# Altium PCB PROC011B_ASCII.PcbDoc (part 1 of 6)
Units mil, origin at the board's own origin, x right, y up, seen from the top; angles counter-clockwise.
Board outline 3304 x 2569 mil, 6 copper layers (TOP, L2-GND1, L3-GND/SIG, L4-GND/SIG, L5-GND2, BOTTOM), stack 55.77 mil thick; 376 components, 289 nets, 1284 pads, 1755 vias.
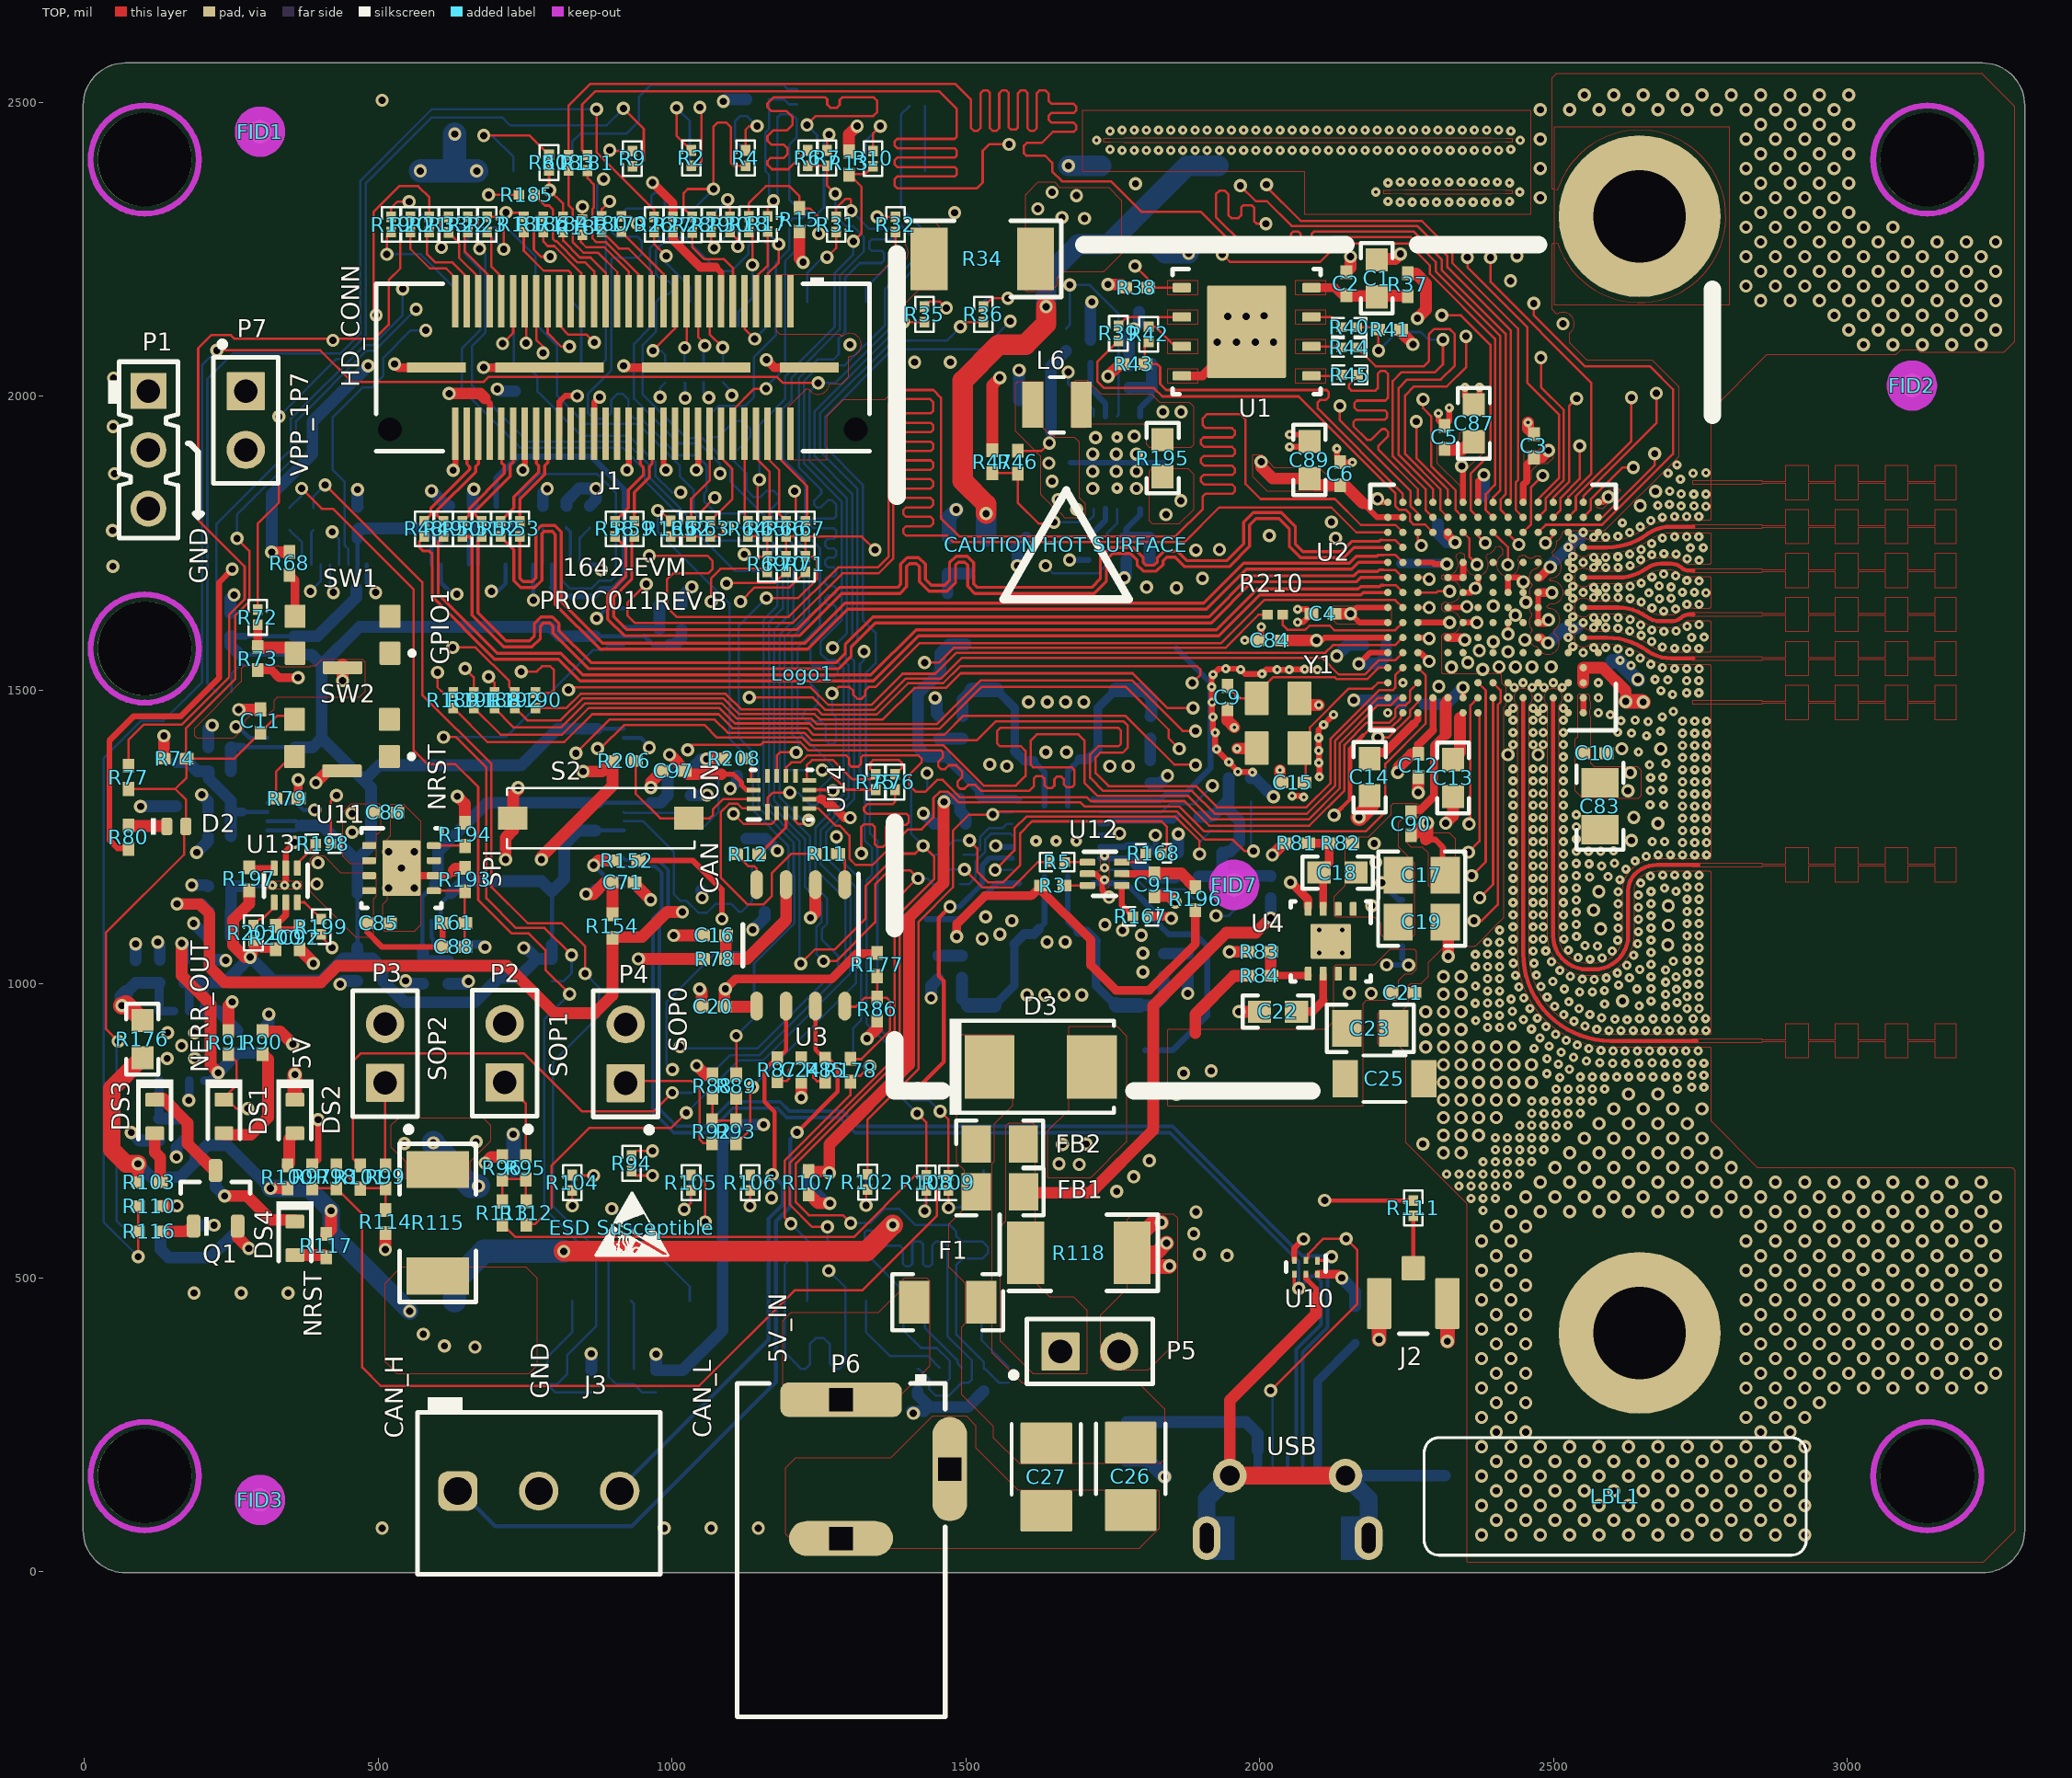
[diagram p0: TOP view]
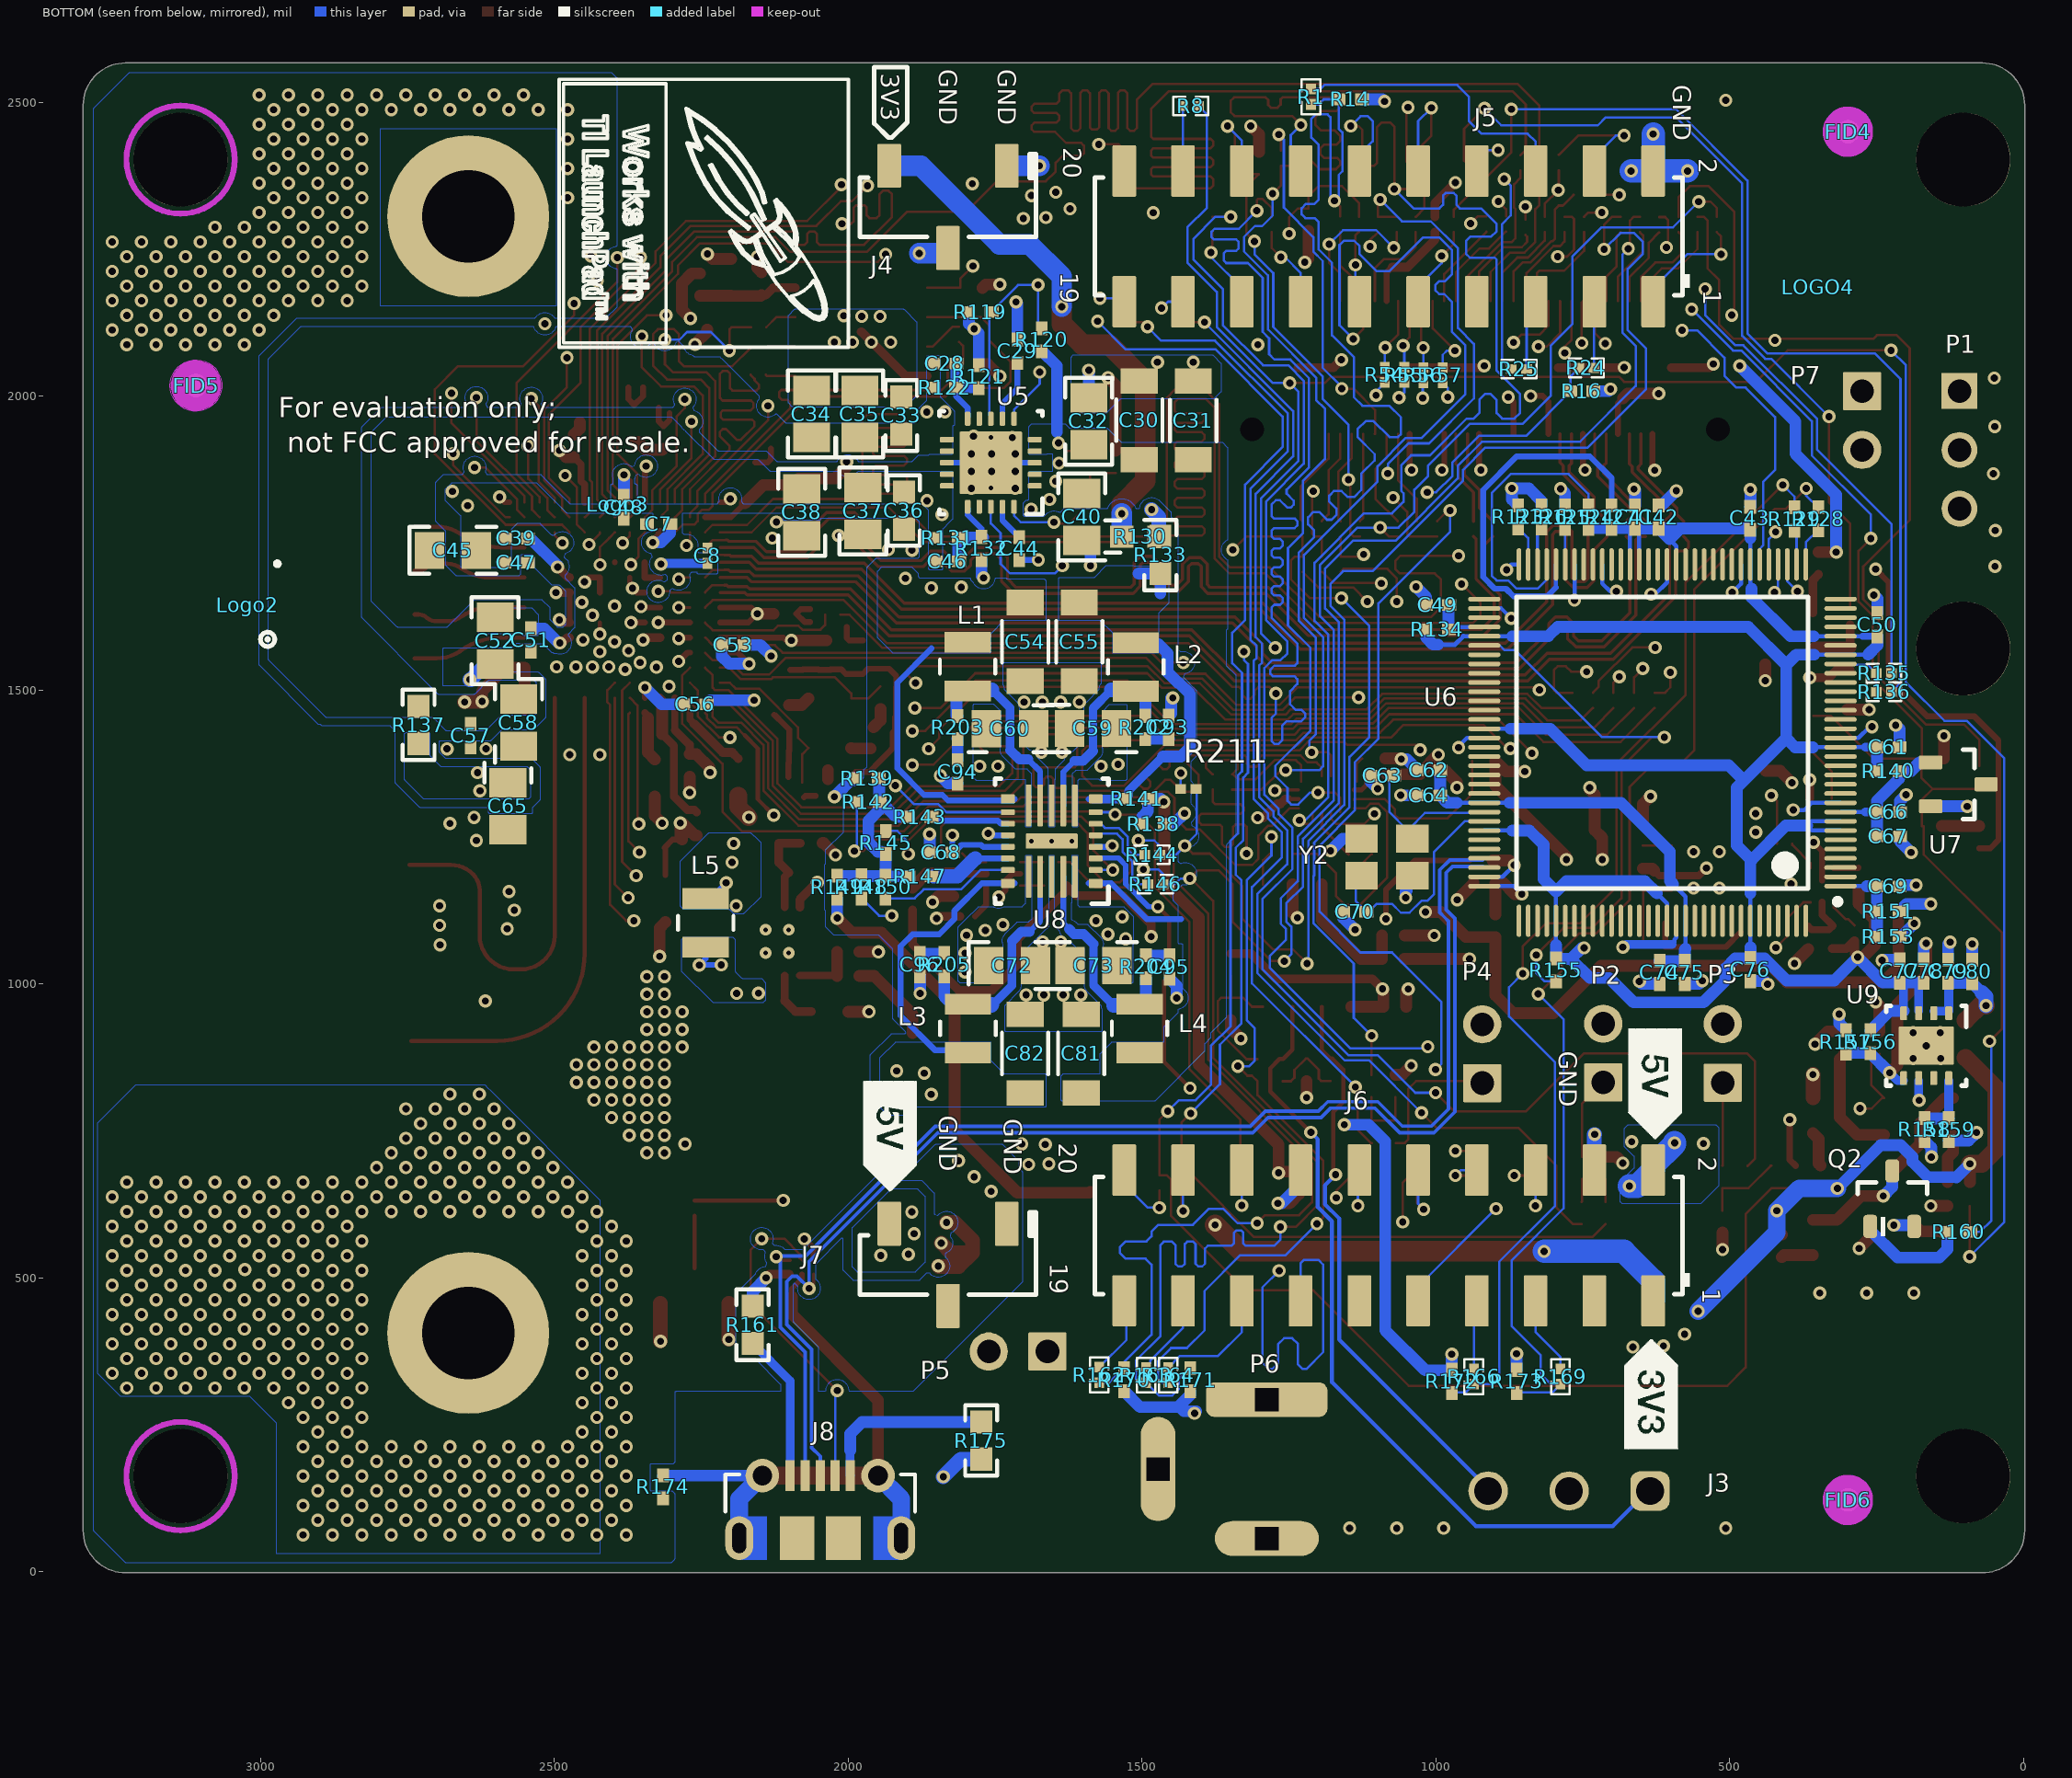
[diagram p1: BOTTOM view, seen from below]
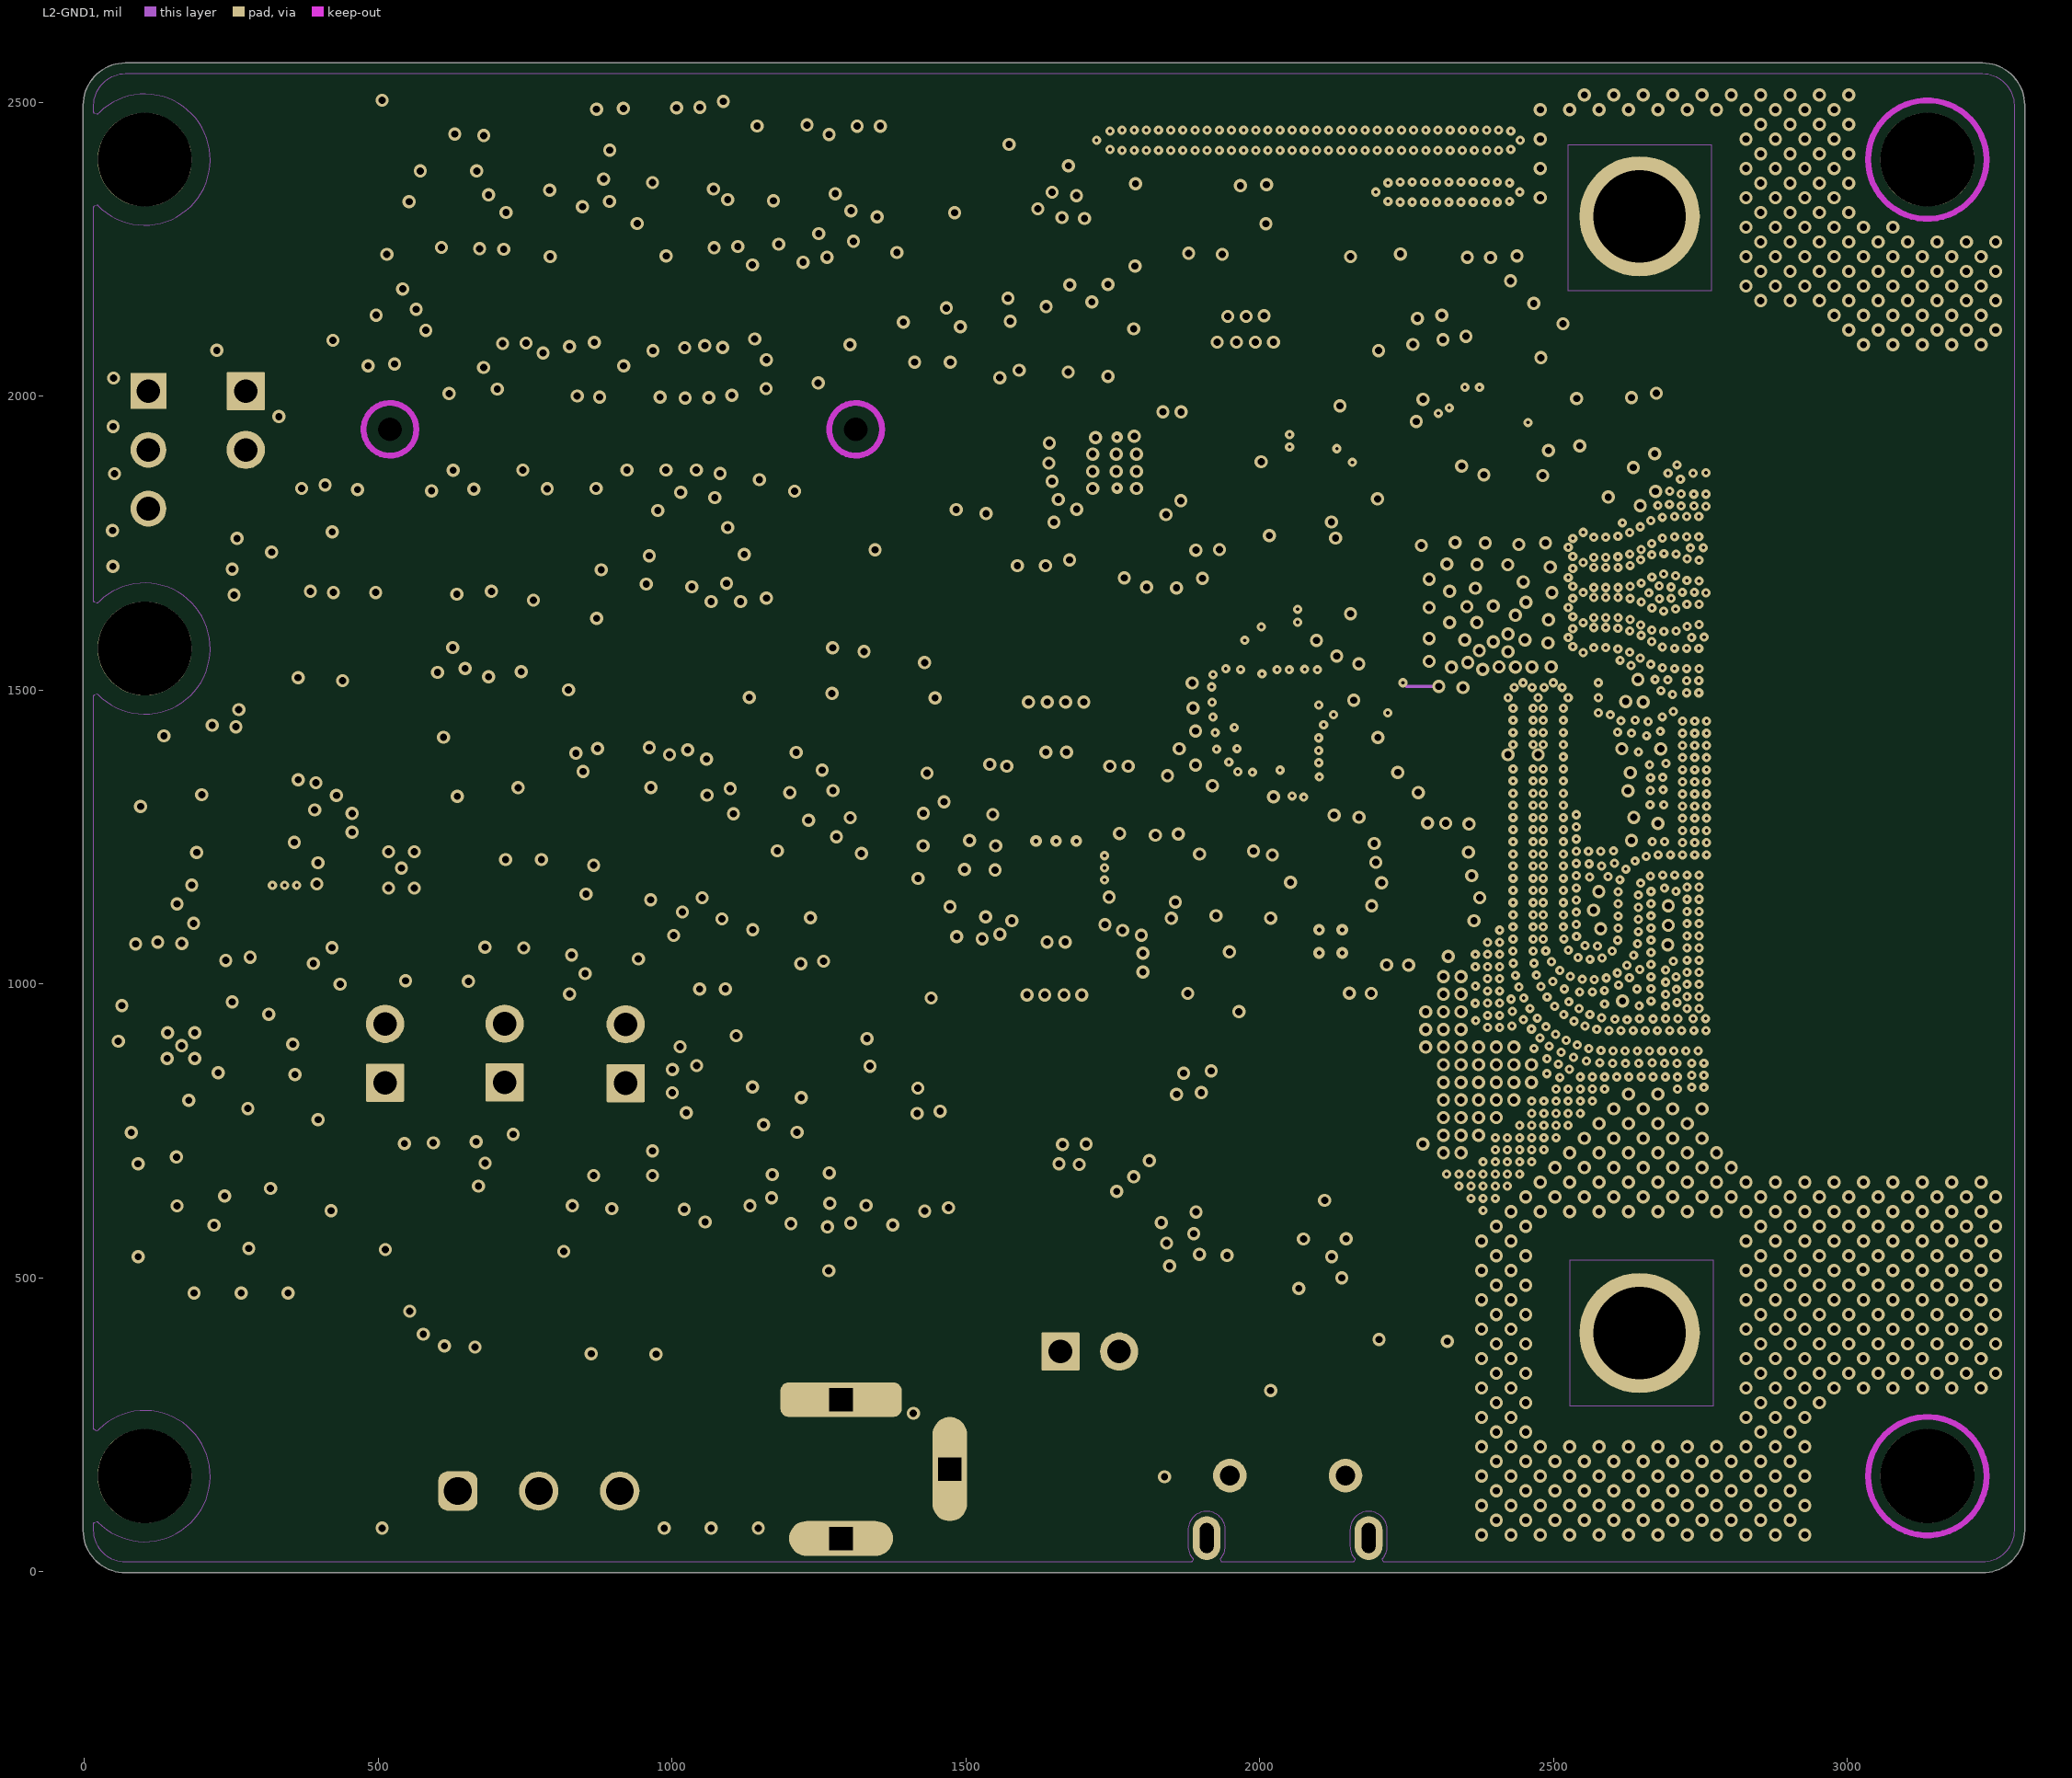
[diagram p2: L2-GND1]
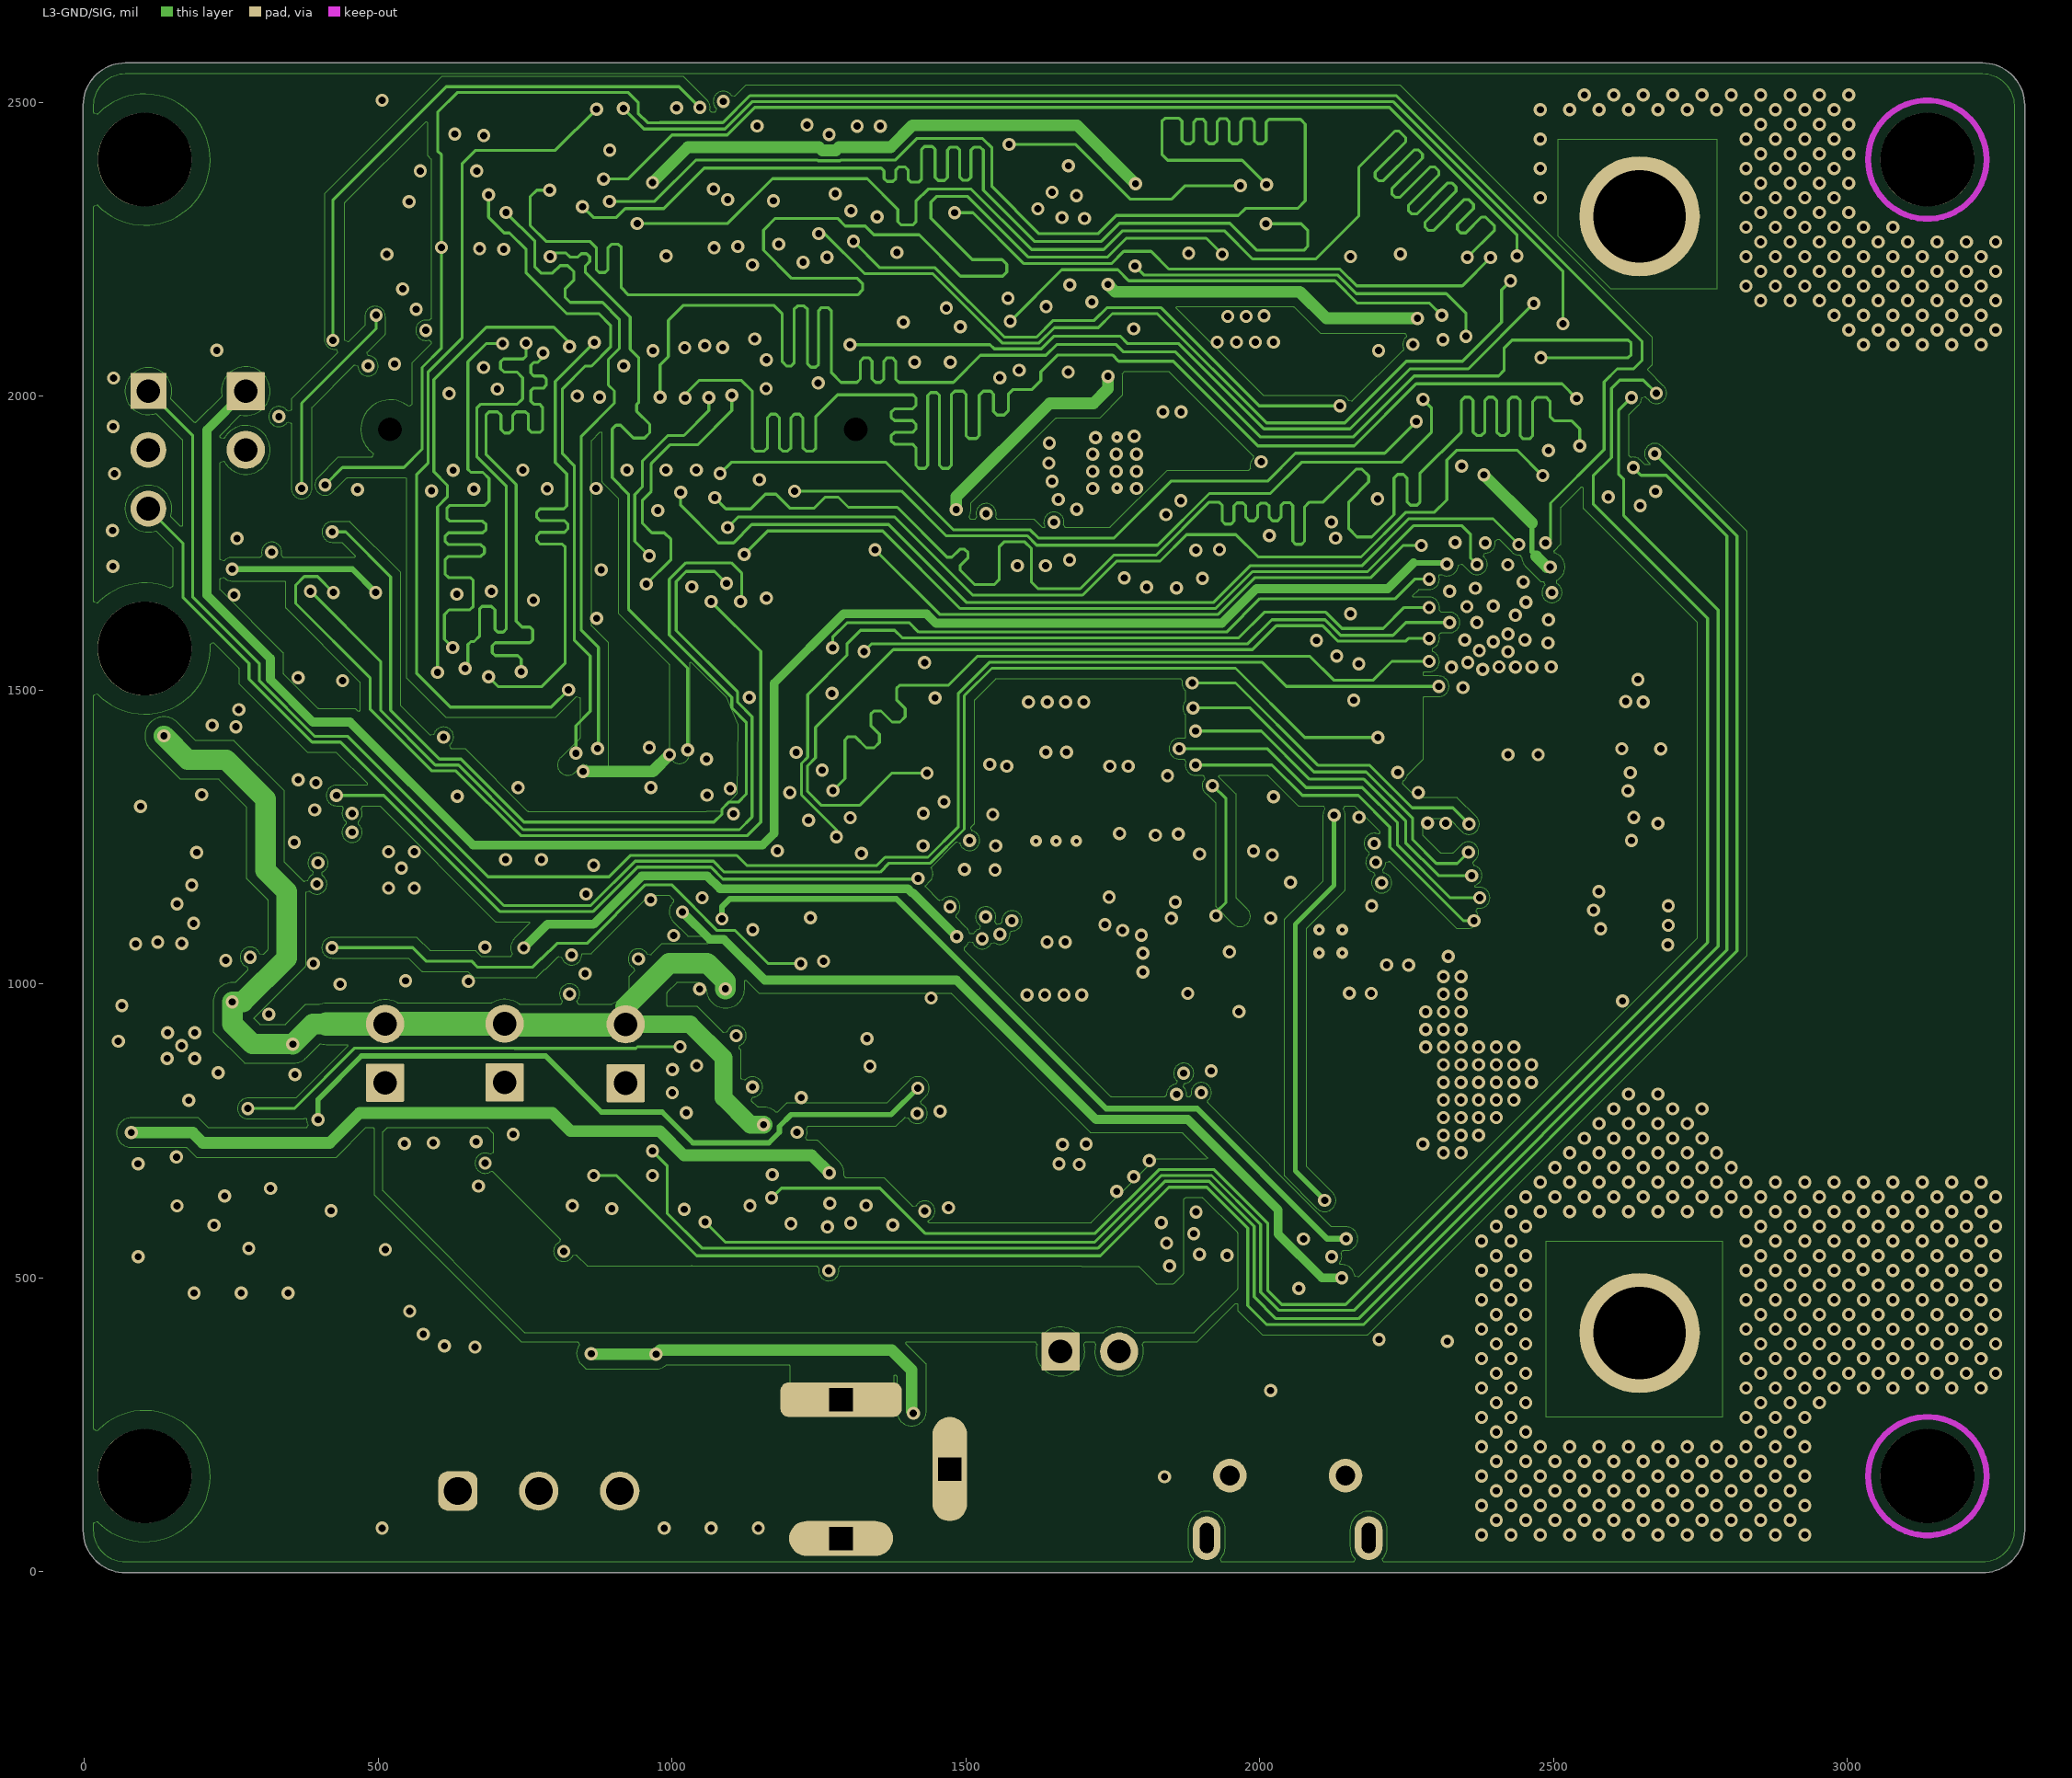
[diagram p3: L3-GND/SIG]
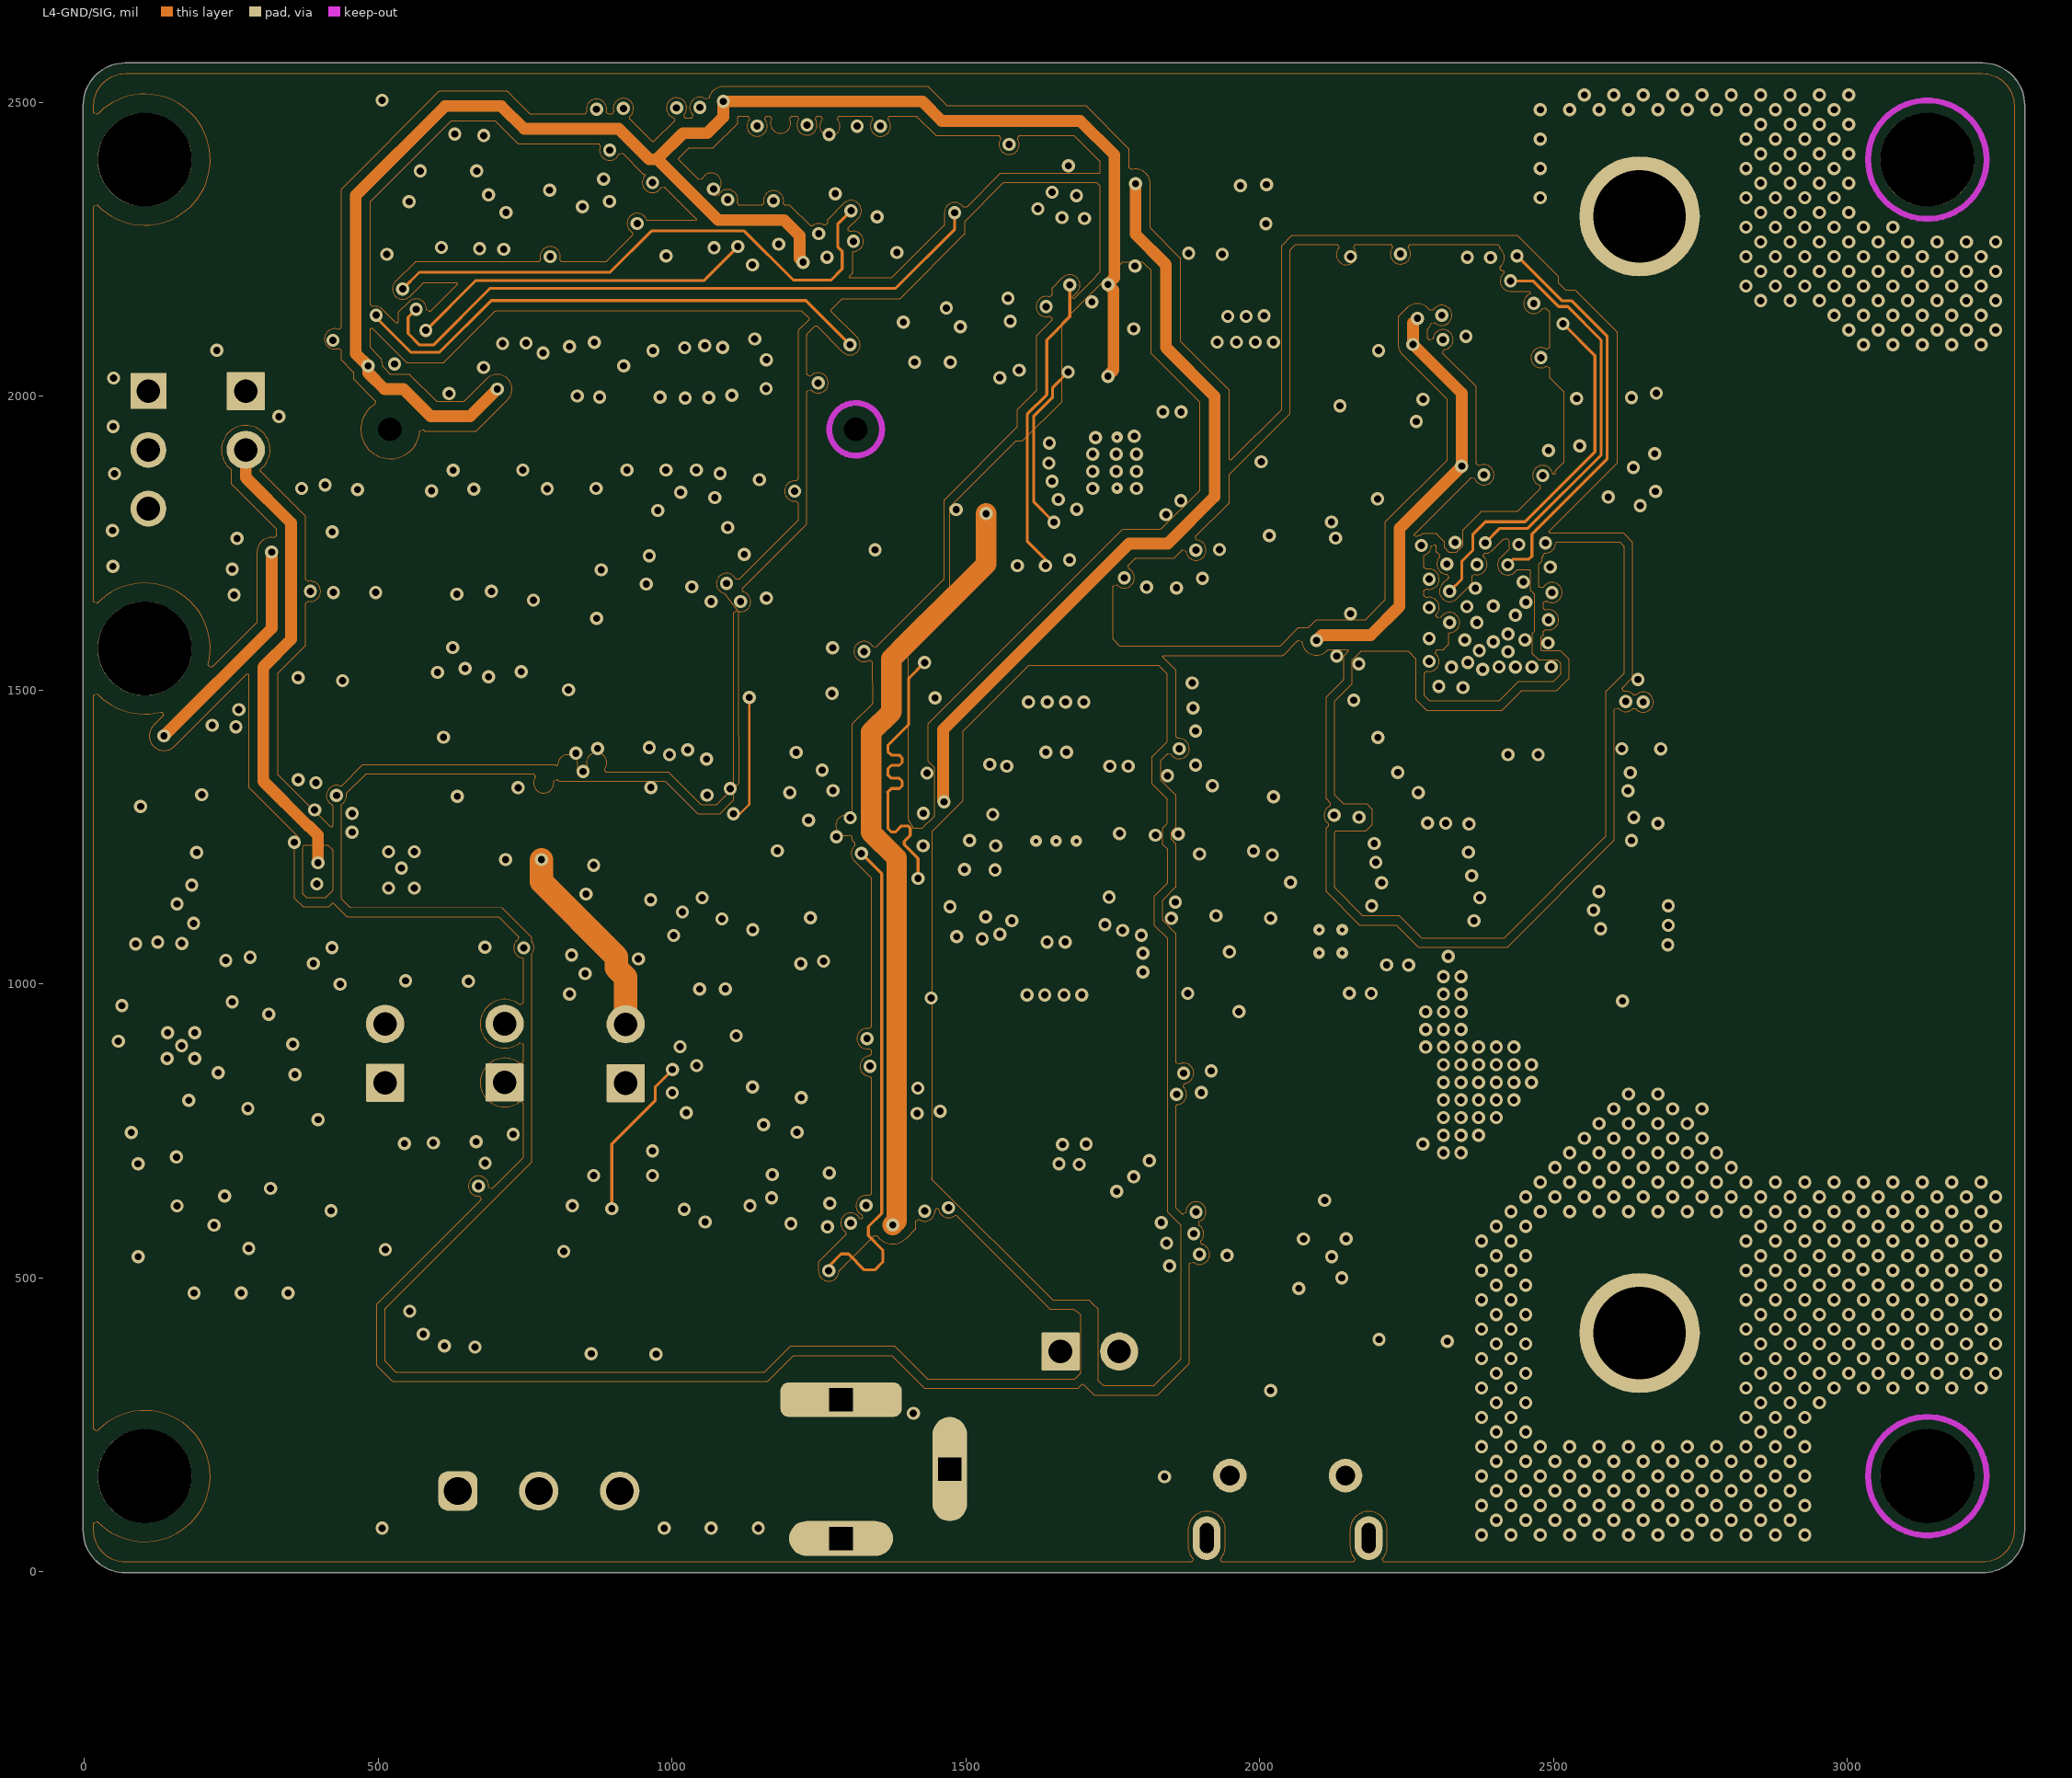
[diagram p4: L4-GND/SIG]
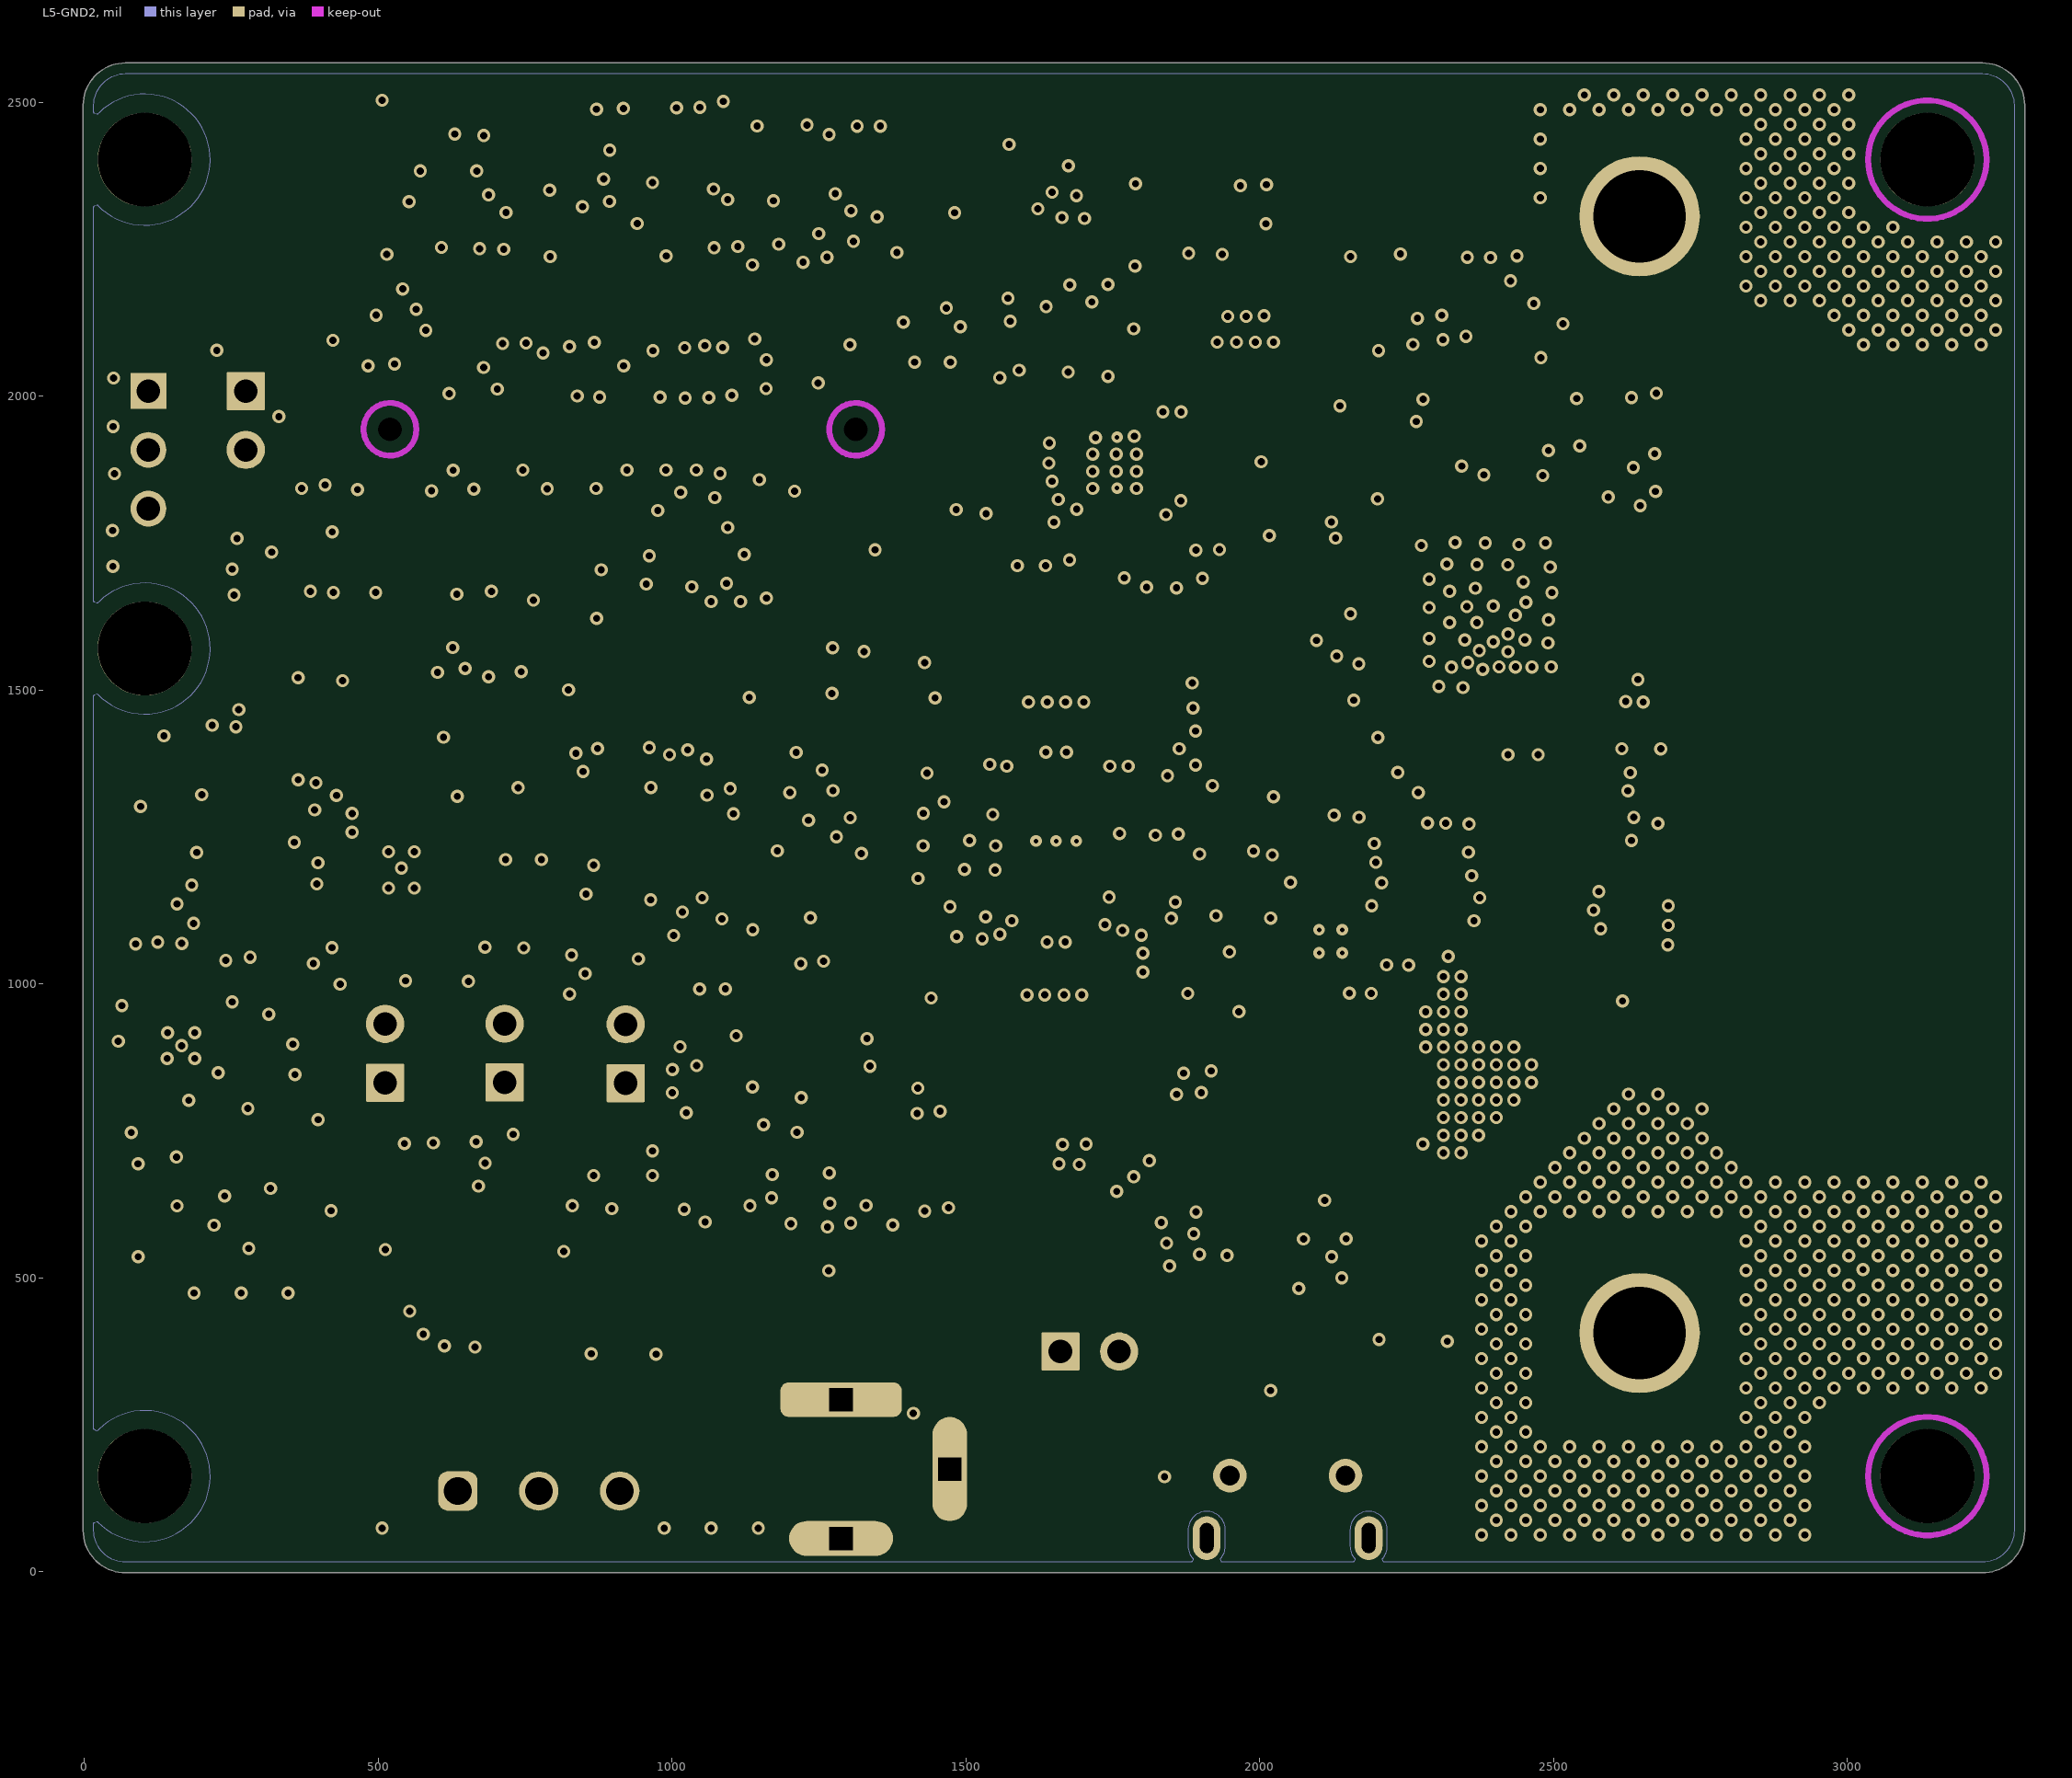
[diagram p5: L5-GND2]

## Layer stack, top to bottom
Top Solder: solder mask 0.8, Solder Resist, Dk 0
TOP: signal copper 1.6
Dielectric1: core 4, RO4835 LOPRO, Dk 3.66
L2-GND1: signal copper 1.4
Dielectric2: prepreg 5.67, 370HR, Dk 3.9
L3-GND/SIG: signal copper 1.2
Dielectric3: core 28, 370HR, Dk 4.36
L4-GND/SIG: signal copper 1.2
Dielectric4: prepreg 5.9, 370HR, Dk 3.9
L5-GND2: signal copper 1.2
Dielectric5: core 4, 370HR, Dk 4.26
BOTTOM: signal copper 1.6
Bottom Solder: solder mask 0.8, Solder Resist, Dk 0

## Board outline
-2,70 ccw(c70,70) 70,-2 3230,-2 ccw(c3230,70) 3302,70 3302,2495 ccw(c3230,2495) 3230,2567 70,2567 ccw(c70,2495) -2,2495

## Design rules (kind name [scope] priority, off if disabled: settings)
AcuteAngle [All] p0: scope1count=1 scope1_0_kind=Board scope1_0_value=Board scope2count=1 scope2_0_kind=Board scope2_0_value=Board commentlength=0 minimum=4.50000000000000E+0001
AcuteAngle [All] p1: minimum=4.50000000000000E+0001 checktracksonly=FALSE
AssemblyTestPointUsage [All] p0: scope1count=1 scope1_0_kind=Board scope1_0_value=Board scope2count=1 scope2_0_kind=Board scope2_0_value=Board commentlength=0
AssemblyTestpoint [All] p0: scope1count=1 scope1_0_kind=Board scope1_0_value=Board scope2count=1 scope2_0_kind=Board scope2_0_value=Board commentlength=0
Clearance COPLANNER [All] p0 off: scope1count=1 scope1_0_kind=Board scope1_0_value=Board scope2count=1 scope2_0_kind=Board scope2_0_value=Board commentlength=59 gap=3 // Protel DXP Scope 1 Expression Was: WithinRoom('COUPLE')
Clearance Clearance_PMIC [All] p0 off: scope1count=1 scope1_0_kind=Board scope1_0_value=Board scope2count=1 scope2_0_kind=Board scope2_0_value=Board commentlength=70 gap=5 // Protel DXP Scope 1 Expression Was: WithinRoom('Copper to PMIC IC')
Clearance same_net_cl_inner [All] p0 off: scope1count=1 scope1_0_kind=Board scope1_0_value=Board scope2count=1 scope2_0_kind=Board scope2_0_value=Board commentlength=61 gap=10 // Protel DXP Scope 1 Expression Was: InLayerClass('layers')
Clearance Clearance_TOP [All] p0: scope1count=1 scope1_0_kind=Layer scope1_0_value=TOP scope2count=1 scope2_0_kind=Board scope2_0_value=Board commentlength=0 gap=10
Clearance Clearance_1 [All] p0 off: scope1count=1 scope1_0_kind=Board scope1_0_value=Board scope2count=1 scope2_0_kind=Board scope2_0_value=Board commentlength=69 gap=6.71 // Protel DXP Scope 1 Expression Was: WithinRoom('DUT') OR InPolygon
Clearance RX_TX_TOP [All] p0: scope1count=1 scope1_0_kind=Layer scope1_0_value=TOP scope2count=1 scope2_0_kind=NetClass scope2_0_value=RX_TX commentlength=0 gap=10
Clearance RX_TX_L25 [All] p0 off: scope1count=1 scope1_0_kind=Board scope1_0_value=Board scope2count=1 scope2_0_kind=NetClass scope2_0_value=RX_TX commentlength=60 gap=10 // Protel DXP Scope 1 Expression Was: InLayerClass('L2_L5')
Clearance RX_TX_L34 [All] p0 off: scope1count=1 scope1_0_kind=Board scope1_0_value=Board scope2count=1 scope2_0_kind=NetClass scope2_0_value=RX_TX commentlength=60 gap=10 // Protel DXP Scope 1 Expression Was: InLayerClass('L3_L4')
Clearance Clearance_L25 [All] p0 off: scope1count=1 scope1_0_kind=Board scope1_0_value=Board scope2count=1 scope2_0_kind=Board scope2_0_value=Board commentlength=60 gap=15 // Protel DXP Scope 1 Expression Was: InLayerClass('L2_L5')
Clearance Clearance_L34 [All] p0 off: scope1count=1 scope1_0_kind=Board scope1_0_value=Board scope2count=1 scope2_0_kind=Board scope2_0_value=Board commentlength=60 gap=15 // Protel DXP Scope 1 Expression Was: InLayerClass('L3_L4')
Clearance Clearance_BTM [All] p0: scope1count=1 scope1_0_kind=Layer scope1_0_value=BOTTOM scope2count=1 scope2_0_kind=Board scope2_0_value=Board commentlength=0 gap=15
Clearance Clearance_L34 [InLayerClass('L3_L4')] p1: gap=15 ignorepadtopadclearanceinfootprint=FALSE except(0: Arc-Hole Track-Hole SMDPad-Hole THPad-Hole Via-Hole Fill-Hole Poly-Hole Region-Hole Text-Hole; 5: Arc-Track Arc-SMDPad Track-Track Track-SMDPad; 5.9: Via-Via; 6: Arc-Arc Arc-THPad Arc-Via Track-THPad Track-Via SMDPad-SMDPad SMDPad-THPad SMDPad-Via SMDPad-Fill SMDPad-Poly THPad-THPad THPad-Via Via-Fill Via-Poly; 10: THPad-Fill THPad-Poly)
Clearance Clearance_PMIC [WithinRoom('Copper to PMIC IC')] p2: gap=5 ignorepadtopadclearanceinfootprint=FALSE except(0: Arc-Hole Track-Hole SMDPad-Hole THPad-Hole Via-Hole Fill-Hole Poly-Hole Region-Hole Text-Hole; 4: Arc-Track Track-Track; 4.5: Track-Via SMDPad-SMDPad)
Clearance Clearance_BTM [OnLayer('BOTTOM')] p3: gap=15 ignorepadtopadclearanceinfootprint=FALSE except(0: Arc-SMDPad Arc-Hole Track-Hole SMDPad-Hole THPad-Hole Via-Hole Fill-Hole Poly-Hole Region-Hole Text-Hole; 4: Track-SMDPad; 4.5: Arc-Via Track-Via; 5: Arc-Arc Arc-Track Track-Track SMDPad-Via; 6: Arc-THPad Track-THPad SMDPad-SMDPad SMDPad-THPad THPad-THPad THPad-Via; 8: Arc-Fill Arc-Poly Track-Fill Track-Poly Via-Fill Via-Poly; 9: SMDPad-Fill SMDPad-Poly THPad-Fill THPad-Poly; 16.6: Via-Via)
Clearance Clearance_L25 [InLayerClass('L2_L5')] p4: gap=15 ignorepadtopadclearanceinfootprint=FALSE except(0: Arc-Hole Track-Hole SMDPad-Hole THPad-Hole Via-Hole Fill-Hole Poly-Hole Region-Hole Text-Hole; 5: Arc-Track Arc-SMDPad Track-Track Track-SMDPad; 6: Arc-Arc Arc-THPad Arc-Via Track-THPad Track-Via SMDPad-SMDPad SMDPad-THPad SMDPad-Via SMDPad-Fill SMDPad-Poly THPad-THPad THPad-Via Via-Via Via-Fill Via-Poly; 10: THPad-Fill THPad-Poly)
Clearance RX_TX_L34 [InLayerClass('L3_L4') vs InNetClass('RX_TX')] p5: gap=10 ignorepadtopadclearanceinfootprint=FALSE except(0: Arc-Hole Track-Hole SMDPad-Hole THPad-Hole Via-Hole Fill-Hole Poly-Hole Region-Hole Text-Hole; 4.86: Via-Via; 5: Arc-SMDPad Track-SMDPad; 6: Arc-Arc Arc-Track Arc-THPad Arc-Via Track-Track Track-THPad Track-Via SMDPad-SMDPad SMDPad-THPad SMDPad-Via SMDPad-Fill SMDPad-Poly THPad-THPad THPad-Via Via-Fill Via-Poly; 15: Arc-Fill Arc-Poly Track-Poly Fill-Fill Fill-Poly Poly-Poly; 16: Track-Fill)
Clearance COPLANNER [WithinRoom('COUPLE')] p6: gap=3 ignorepadtopadclearanceinfootprint=FALSE except(0: Arc-Hole Track-Hole SMDPad-Hole THPad-Hole Via-Hole Fill-Hole Poly-Hole Region-Hole Text-Hole)
Clearance Clearance_1 [WithinRoom('DUT') OR InPolygon] p7: gap=6.71 ignorepadtopadclearanceinfootprint=FALSE except(0: Arc-Hole Track-Hole SMDPad-Hole THPad-Hole Via-Hole Fill-Hole Poly-Hole Region-Hole Text-Hole; 4: Track-Track Track-SMDPad Track-Via SMDPad-Via; 6.6: Via-Region; 6.72: Arc-Region Arc-Text Track-Region Track-Text SMDPad-Region SMDPad-Text THPad-Region THPad-Text Via-Text Fill-Region Fill-Text Poly-Region Poly-Text Region-Region Region-Text Text-Text; 9: SMDPad-Poly; 10: THPad-Poly)
Clearance Clearance_TOP [OnLayer('TOP')] p8: gap=10 ignorepadtopadclearanceinfootprint=FALSE except(0: Arc-SMDPad Arc-Hole Track-Hole SMDPad-Hole THPad-Hole Via-Hole Fill-Hole Poly-Hole Region-Hole Text-Hole; 4: Arc-Arc Arc-Track Arc-Via Track-Track Track-Via; 5: Track-SMDPad SMDPad-Via; 6: Arc-THPad Track-THPad SMDPad-SMDPad SMDPad-THPad THPad-THPad THPad-Via Via-Fill Via-Poly; 8: Arc-Fill Arc-Poly Track-Fill Track-Poly; 9: SMDPad-Fill SMDPad-Poly THPad-Fill THPad-Poly; 15: Fill-Fill Fill-Poly Poly-Poly; 15.4: Via-Via)
Clearance RX_TX_L25 [InLayerClass('L2_L5') vs InNetClass('RX_TX')] p9: gap=10 ignorepadtopadclearanceinfootprint=FALSE except(0: Arc-Hole Track-Hole SMDPad-Hole THPad-Hole Via-Hole Fill-Hole Poly-Hole Region-Hole Text-Hole; 5: Arc-SMDPad Track-SMDPad; 6: Arc-Arc Arc-Track Arc-THPad Arc-Via Track-Track Track-THPad Track-Via SMDPad-SMDPad SMDPad-THPad SMDPad-Via SMDPad-Fill SMDPad-Poly THPad-THPad THPad-Via Via-Fill Via-Poly; 9.1: Via-Via; 15: Arc-Fill Arc-Poly Track-Fill Track-Poly Fill-Fill Fill-Poly Poly-Poly)
Clearance RX_TX_TOP [OnLayer('TOP') vs InNetClass('RX_TX')] p10: gap=10 ignorepadtopadclearanceinfootprint=FALSE except(0: Arc-Hole Track-Hole SMDPad-Hole THPad-Hole Via-Hole Fill-Hole Poly-Hole Region-Hole Text-Hole; 4: Arc-Track Arc-SMDPad Track-Track Track-SMDPad SMDPad-Via; 6: Arc-THPad Track-THPad SMDPad-SMDPad SMDPad-THPad THPad-THPad THPad-Via THPad-Fill THPad-Poly; 6.7: Arc-Fill Arc-Poly Track-Fill Track-Poly; 6.72: Arc-Via Track-Via Via-Fill Via-Poly; 9: SMDPad-Fill SMDPad-Poly; 15.4: Via-Via)
Clearance same_net_cl_inner [InLayerClass('layers')] p11: gap=10 ignorepadtopadclearanceinfootprint=FALSE except(0: Arc-Hole Track-Hole SMDPad-Hole THPad-Hole Via-Hole Fill-Hole Poly-Hole Region-Hole Text-Hole; 5: Arc-THPad Track-Track Track-SMDPad Track-THPad SMDPad-SMDPad SMDPad-THPad THPad-THPad; 6: Track-Via SMDPad-Via THPad-Via Via-Via Via-Fill Via-Poly; 15: Arc-Fill Arc-Poly Fill-Fill Fill-Poly Poly-Poly)
ComponentClearance ComponentClearance_1 [All] p0: scope1count=1 scope1_0_kind=Component scope1_0_value=R130 scope2count=1 scope2_0_kind=Component scope2_0_value=R133 commentlength=0 gap=0 collisioncheckmode=3
ComponentClearance [All] p0: scope1count=1 scope1_0_kind=Board scope1_0_value=Board scope2count=1 scope2_0_kind=Board scope2_0_value=Board commentlength=0 gap=10 collisioncheckmode=3
ComponentClearance ComponentClearance_1 [InComponent('R130') vs InComponent('R133')] p1: gap=0 collisioncheckmode=3 verticalgap=0 showdistances=FALSE
ComponentClearance [All] p2: gap=10 collisioncheckmode=3 verticalgap=10 showdistances=FALSE
DiffPairsRouting Diff_100ohm [All] p0 off: scope1count=1 scope1_0_kind=Board scope1_0_value=Board scope2count=1 scope2_0_kind=Board scope2_0_value=Board commentlength=72 // Protel DXP Scope 1 Expression Was: InDifferentialPairClass('100ohm')
DiffPairsRouting Diff_90ohm [All] p0 off: scope1count=1 scope1_0_kind=Board scope1_0_value=Board scope2count=1 scope2_0_kind=Board scope2_0_value=Board commentlength=72 // Protel DXP Scope 1 Expression Was: InDifferentialPairClass('90_OHM')
DiffPairsRouting [All] p0: scope1count=1 scope1_0_kind=Board scope1_0_value=Board scope2count=1 scope2_0_kind=Board scope2_0_value=Board commentlength=0
DiffPairsRouting Diff_100ohm [InDifferentialPairClass('100ohm')] p1: maxlimit=5 minlimit=5 mostfreqgap=5 toplayer_minwidth=4 toplayer_maxwidth=5.2 toplayer_prefwidth=5.2 midlayer1_minwidth=4 midlayer1_maxwidth=5.2 midlayer1_prefwidth=5.2 midlayer2_minwidth=4 midlayer2_maxwidth=5.2 midlayer2_prefwidth=5.2 midlayer3_minwidth=4 midlayer3_maxwidth=5.2 midlayer3_prefwidth=5.2 midlayer4_minwidth=4 midlayer4_maxwidth=5.2 midlayer4_prefwidth=5.2 bottomlayer_minwidth=4 bottomlayer_maxwidth=5.2 bottomlayer_prefwidth=5.2 maxuncoupledlength=500
DiffPairsRouting Diff_90ohm [InDifferentialPairClass('90_OHM')] p2: maxlimit=5 minlimit=5 mostfreqgap=5 toplayer_minwidth=5.2 toplayer_maxwidth=5.2 toplayer_prefwidth=5.2 midlayer1_minwidth=6 midlayer1_maxwidth=6 midlayer1_prefwidth=6 midlayer2_minwidth=6 midlayer2_maxwidth=6 midlayer2_prefwidth=6 midlayer3_minwidth=6 midlayer3_maxwidth=6 midlayer3_prefwidth=6 midlayer4_minwidth=6 midlayer4_maxwidth=6 midlayer4_prefwidth=6 bottomlayer_minwidth=6 bottomlayer_maxwidth=6 bottomlayer_prefwidth=6 maxuncoupledlength=500
DiffPairsRouting [All] p3: maxlimit=5 minlimit=4 mostfreqgap=5 toplayer_minwidth=4 toplayer_maxwidth=6 toplayer_prefwidth=5.2 midlayer1_minwidth=4 midlayer1_maxwidth=6 midlayer1_prefwidth=5.2 midlayer2_minwidth=4 midlayer2_maxwidth=6 midlayer2_prefwidth=5.2 midlayer3_minwidth=4 midlayer3_maxwidth=6 midlayer3_prefwidth=5.2 midlayer4_minwidth=4 midlayer4_maxwidth=6 midlayer4_prefwidth=5.2 bottomlayer_minwidth=4 bottomlayer_maxwidth=6 bottomlayer_prefwidth=5.2 maxuncoupledlength=500
FabricationTestPointUsage [All] p0: scope1count=1 scope1_0_kind=Board scope1_0_value=Board scope2count=1 scope2_0_kind=Board scope2_0_value=Board commentlength=0 valid=0 allowmultiple=FALSE
FabricationTestpoint [All] p0: scope1count=1 scope1_0_kind=Board scope1_0_value=Board scope2count=1 scope2_0_kind=Board scope2_0_value=Board commentlength=0 side=3 testpointundercomponent=TRUE minsize=40 maxsize=100 preferedsize=60 minholesize=0 maxholesize=40 preferedholesize=32 testpointgrid=1
FanoutControl Fanout_Default [All] p0: scope1count=1 scope1_0_kind=Board scope1_0_value=Board scope2count=1 scope2_0_kind=Board scope2_0_value=Board commentlength=30 // Fanout_Default (Default Rule)
FanoutControl Fanout_Small [All] p0 off: scope1count=1 scope1_0_kind=Board scope1_0_value=Board scope2count=1 scope2_0_kind=Board scope2_0_value=Board commentlength=84 // Protel DXP Scope 1 Expression Was: (CompPinCount < 5)   Fanout_Small (Default Rule)
FanoutControl Fanout_SOIC [All] p0 off: scope1count=1 scope1_0_kind=Board scope1_0_value=Board scope2count=1 scope2_0_kind=Board scope2_0_value=Board commentlength=71 // Protel DXP Scope 1 Expression Was: IsSOIC   Fanout_SOIC (Default Rule)
FanoutControl Fanout_LCC [All] p0 off: scope1count=1 scope1_0_kind=Board scope1_0_value=Board scope2count=1 scope2_0_kind=Board scope2_0_value=Board commentlength=69 // Protel DXP Scope 1 Expression Was: IsLCC   Fanout_LCC (Default Rule)
FanoutControl Fanout_BGA [All] p0 off: scope1count=1 scope1_0_kind=Board scope1_0_value=Board scope2count=1 scope2_0_kind=Board scope2_0_value=Board commentlength=69 // Protel DXP Scope 1 Expression Was: IsBGA   Fanout_BGA (Default Rule)
Height [All] p0: scope1count=1 scope1_0_kind=Board scope1_0_value=Board scope2count=1 scope2_0_kind=Board scope2_0_value=Board commentlength=0
HoleSize [All] p0: scope1count=1 scope1_0_kind=Board scope1_0_value=Board scope2count=1 scope2_0_kind=Board scope2_0_value=Board commentlength=0 absolutevalues=TRUE maxlimit=200 minlimit=5.9 maxpercent=80.000 minpercent=20.000
HoleSize [All] p1: absolutevalues=TRUE maxlimit=200 minlimit=5.9 maxpercent=80.000 minpercent=20.000
HoleToHoleClearance [All] p0: scope1count=1 scope1_0_kind=Board scope1_0_value=Board scope2count=1 scope2_0_kind=Board scope2_0_value=Board commentlength=0
LayerPairs [All] p0: scope1count=1 scope1_0_kind=Board scope1_0_value=Board scope2count=1 scope2_0_kind=Board scope2_0_value=Board commentlength=0 enforce=TRUE
Length DATA0_15 [All] p0 off: scope1count=1 scope1_0_kind=Board scope1_0_value=Board scope2count=1 scope2_0_kind=Board scope2_0_value=Board commentlength=66 maxlimit=3530 minlimit=3200 // Protel DXP Scope 1 Expression Was: InxSignalClass('D0_TO_D15')
Length 100_OHM [All] p0 off: scope1count=1 scope1_0_kind=Board scope1_0_value=Board scope2count=1 scope2_0_kind=Board scope2_0_value=Board commentlength=70 maxlimit=2057 minlimit=2052 // Protel DXP Scope 1 Expression Was: InDifferentialPairClass('DIIF')
Length 90_OHM [All] p0 off: scope1count=1 scope1_0_kind=Board scope1_0_value=Board scope2count=1 scope2_0_kind=Board scope2_0_value=Board commentlength=72 maxlimit=100000 minlimit=0 // Protel DXP Scope 1 Expression Was: InDifferentialPairClass('90_OHM')
Length LVDS [All] p0: scope1count=1 scope1_0_kind=NetClass scope1_0_value=LVDS scope2count=1 scope2_0_kind=Board scope2_0_value=Board commentlength=0 maxlimit=1890 minlimit=1860
Length QSPI [All] p0: scope1count=1 scope1_0_kind=NetClass scope1_0_value=QSPI scope2count=1 scope2_0_kind=Board scope2_0_value=Board commentlength=0 maxlimit=800 minlimit=600
Length SPI_1 [All] p0: scope1count=1 scope1_0_kind=NetClass scope1_0_value=SPI1 scope2count=1 scope2_0_kind=Board scope2_0_value=Board commentlength=0 maxlimit=1600 minlimit=1390
Length SPI_2 [All] p0 off: scope1count=1 scope1_0_kind=Board scope1_0_value=Board scope2count=1 scope2_0_kind=Board scope2_0_value=Board commentlength=62 maxlimit=3500 minlimit=3000 // Protel DXP Scope 1 Expression Was: InxSignalClass('spi_2')
Length DIFF_1 [All] p0: scope1count=1 scope1_0_kind=NetClass scope1_0_value=100_OHM scope2count=1 scope2_0_kind=Board scope2_0_value=Board commentlength=0 maxlimit=2055 minlimit=2051
Length DIFF_2 [All] p0 off: scope1count=1 scope1_0_kind=Board scope1_0_value=Board scope2count=1 scope2_0_kind=Board scope2_0_value=Board commentlength=72 maxlimit=2201 minlimit=2201 // Protel DXP Scope 1 Expression Was: InDifferentialPairClass('90_OHM')
Length DIFF_2 [InDifferentialPairClass('90_OHM')] p1: maxlimit=2201 minlimit=2201
Length DIFF_1 [InNetClass('100_OHM')] p2: maxlimit=2055 minlimit=2051
Length SPI_2 [InxSignalClass('spi_2')] p3: maxlimit=3500 minlimit=3000
Length SPI_1 [InNetClass('SPI1')] p4: maxlimit=1600 minlimit=1390
Length QSPI [InNetClass('QSPI')] p5: maxlimit=800 minlimit=600
Length LVDS [InNetClass('LVDS')] p6: maxlimit=1890 minlimit=1860
Length 90_OHM [InDifferentialPairClass('90_OHM')] p7: maxlimit=100000 minlimit=0
Length 100_OHM [InDifferentialPairClass('DIIF')] p8: maxlimit=2057 minlimit=2052
Length DATA0_15 [InxSignalClass('D0_TO_D15')] p9: maxlimit=3530 minlimit=3200
MinimumAnnularRing [All] p0: scope1count=1 scope1_0_kind=Board scope1_0_value=Board scope2count=1 scope2_0_kind=Board scope2_0_value=Board commentlength=0 minimumring=3.9
MinimumAnnularRing [All] p1: minimumring=3.9
MinimumSolderMaskSliver [All] p0: scope1count=1 scope1_0_kind=Board scope1_0_value=Board scope2count=1 scope2_0_kind=Board scope2_0_value=Board commentlength=0
MinimumSolderMaskSliver [All] p1: minsoldermaskwidth=3.9
NetAntennae [All] p0: scope1count=1 scope1_0_kind=Board scope1_0_value=Board scope2count=1 scope2_0_kind=Board scope2_0_value=Board commentlength=0
PasteMaskExpansion [All] p0: scope1count=1 scope1_0_kind=Board scope1_0_value=Board scope2count=1 scope2_0_kind=Board scope2_0_value=Board commentlength=0 expansion=0
PlaneClearance [All] p0: scope1count=1 scope1_0_kind=Board scope1_0_value=Board scope2count=1 scope2_0_kind=Board scope2_0_value=Board commentlength=0 clearance=20
PlaneConnect [All] p0: scope1count=1 scope1_0_kind=Board scope1_0_value=Board scope2count=1 scope2_0_kind=Board scope2_0_value=Board commentlength=0 planeconnectstyle=Direct reliefexpansion=20 reliefentries=4 reliefconductorwidth=10 reliefairgap=10
PlaneConnect [All] p1: planeconnectstyle=Direct reliefexpansion=20 reliefentries=4 reliefconductorwidth=10 reliefairgap=10
PolygonConnect [All] p0: scope1count=1 scope1_0_kind=Board scope1_0_value=Board scope2count=1 scope2_0_kind=Board scope2_0_value=Board commentlength=0 connectstyle=Direct reliefconductorwidth=10 reliefentries=4 polygonreliefangle="90 Angle"
PolygonConnect [All] p1: connectstyle=Direct reliefconductorwidth=10 reliefentries=4 polygonreliefangle="90 Angle" airgapwidth=10
RoomDefinition COUPLE [All] p0 off: scope1count=1 scope1_0_kind=Board scope1_0_value=Board scope2count=1 scope2_0_kind=Board scope2_0_value=Board commentlength=63 region_x1=506229300 region_y1=514691500 region_x2=513975700 region_y2=516601600 confinementstyle=ConfineOut // Protel DXP Scope 1 Expression Was: WithinRoom('CO_PLANNER')
RoomDefinition "Copper to PMIC IC" [All] p0: scope1count=1 scope1_0_kind=Board scope1_0_value=Board scope2count=1 scope2_0_kind=Board scope2_0_value=Board commentlength=0 region_x1=504460000 region_y1=502506444 region_x2=507211000 region_y2=505645000 confinementstyle=ConfineIn
RoomDefinition DUT [All] p0: scope1count=1 scope1_0_kind=ComponentClass scope1_0_value=DUT scope2count=1 scope2_0_kind=Board scope2_0_value=Board commentlength=0 region_x1=511290000 region_y1=499260000 region_x2=521360000 region_y2=510750000 confinementstyle=ConfineIn
RoomDefinition COUPLE [WithinRoom('CO_PLANNER')] p1: confinementstyle=ConfineOut formatcopy=TRUE lockcomponents=FALSE outline 1695.28,2494.16 1696.02,2493.42 2464.32,2493.42 2464.32,2306.04 2461.43,2303.15 2077.72,2303.15 2068.43,2312.44 2068.43,2376.81 1697.78,2376.81 1689.68,2384.91
RoomDefinition "Copper to PMIC IC" [All] p2: confinementstyle=ConfineIn formatcopy=TRUE lockcomponents=FALSE outline 1512.75,1398.5 1777.77,1398.5 1787.85,1386.9 1784.75,1383.33 1784.75,1090.6 1779.58,1084.64 1554.38,1084.64 1516.75,1127.96 1516.75,1393.9
RoomDefinition DUT [InComponentClass('DUT')] p3: confinementstyle=ConfineIn formatcopy=TRUE lockcomponents=FALSE outline 2245.75,1898 2256.75,1909 3176.75,1909 3202.75,1883 3202.75,782 3180.75,760 2483.75,760 2408.75,835 2408.75,1377 2371.75,1414 2258.75,1414 2195.75,1477 2195.75,1875 2218.75,1898
RoutingCorners [All] p0: scope1count=1 scope1_0_kind=Board scope1_0_value=Board scope2count=1 scope2_0_kind=Board scope2_0_value=Board commentlength=0 cornerstyle=45-Degree minsetback=100 maxsetback=100
RoutingLayers [All] p0: scope1count=1 scope1_0_kind=Board scope1_0_value=Board scope2count=1 scope2_0_kind=Board scope2_0_value=Board commentlength=0 top layer=Automatic mid layer 1=Automatic mid layer 2=Automatic mid layer 3=Automatic mid layer 4=Automatic bottom layer=Automatic
RoutingPriority [All] p0: scope1count=1 scope1_0_kind=Board scope1_0_value=Board scope2count=1 scope2_0_kind=Board scope2_0_value=Board commentlength=0
RoutingTopology [All] p0: scope1count=1 scope1_0_kind=Board scope1_0_value=Board scope2count=1 scope2_0_kind=Board scope2_0_value=Board commentlength=0 topology=Shortest
RoutingVias [All] p0: scope1count=1 scope1_0_kind=Board scope1_0_value=Board scope2count=1 scope2_0_kind=Board scope2_0_value=Board commentlength=0 holewidth=12.2 width=22.4 viastyle="Through Hole" minholewidth=5.9 minwidth=13 maxholewidth=24 maxwidth=50
RoutingVias [All] p1: holewidth=12.2 width=22.4 viastyle="Through Hole" minholewidth=5.9 minwidth=13 maxholewidth=24 maxwidth=50
ShortCircuit [All] p0: scope1count=1 scope1_0_kind=Board scope1_0_value=Board scope2count=1 scope2_0_kind=Board scope2_0_value=Board commentlength=0 allowed=FALSE
SilkToBoardRegionClearance [All] p0: scope1count=1 scope1_0_kind=Board scope1_0_value=Board scope2count=1 scope2_0_kind=Board scope2_0_value=Board commentlength=0
SilkToSilkClearance [All] p0: scope1count=1 scope1_0_kind=Board scope1_0_value=Board scope2count=1 scope2_0_kind=Board scope2_0_value=Board commentlength=0
SilkToSilkClearance [All] p1: silktosilkclearance=3
SilkToSolderMaskClearance SilkscreenOverComponentPads [All] p0 off: scope1count=1 scope1_0_kind=Board scope1_0_value=Board scope2count=1 scope2_0_kind=Board scope2_0_value=Board commentlength=44 // Protel DXP Scope 1 Expression Was: IsPad
SilkToSolderMaskClearance [All] p0 off: scope1count=1 scope1_0_kind=Board scope1_0_value=Board scope2count=1 scope2_0_kind=Board scope2_0_value=Board commentlength=44 // Protel DXP Scope 1 Expression Was: IsPad
SilkToSolderMaskClearance [IsPad] p1: minsilkscreentomaskgap=4 clearancetoexposedcopper=FALSE
SilkToSolderMaskClearance SilkscreenOverComponentPads [IsPad] p2: minsilkscreentomaskgap=5 clearancetoexposedcopper=TRUE
SolderMaskExpansion [All] p0: scope1count=1 scope1_0_kind=Board scope1_0_value=Board scope2count=1 scope2_0_kind=Board scope2_0_value=Board commentlength=0 expansion=0
SolderMaskExpansion [All] p1: expansion=0
UnRoutedNet [All] p0: scope1count=1 scope1_0_kind=Board scope1_0_value=Board scope2count=1 scope2_0_kind=Board scope2_0_value=Board commentlength=0
UnpouredPolygon [All] p0: scope1count=1 scope1_0_kind=Board scope1_0_value=Board scope2count=1 scope2_0_kind=Board scope2_0_value=Board commentlength=0
ViasUnderSMD [All] p0: scope1count=1 scope1_0_kind=Board scope1_0_value=Board scope2count=1 scope2_0_kind=Board scope2_0_value=Board commentlength=0 allowed=FALSE
ViasUnderSMD [All] p1: allowed=FALSE
Width Width_1 [All] p0: scope1count=1 scope1_0_kind=Board scope1_0_value=Board scope2count=1 scope2_0_kind=Board scope2_0_value=Board commentlength=0 maxlimit=100 minlimit=4 preferedwidth=10
Width Width_room1 [All] p0: scope1count=1 scope1_0_kind=Board scope1_0_value=Board scope2count=1 scope2_0_kind=Board scope2_0_value=Board commentlength=0 maxlimit=100 minlimit=10 preferedwidth=20
Width Width_100 [All] p0 off: scope1count=1 scope1_0_kind=Board scope1_0_value=Board scope2count=1 scope2_0_kind=Board scope2_0_value=Board commentlength=70 maxlimit=5.2 minlimit=5 preferedwidth=5 // Protel DXP Scope 1 Expression Was: InDifferentialPairClass('DIIF')
Width Width_90ohm [All] p0 off: scope1count=1 scope1_0_kind=Board scope1_0_value=Board scope2count=1 scope2_0_kind=Board scope2_0_value=Board commentlength=72 maxlimit=6 minlimit=5 preferedwidth=5 // Protel DXP Scope 1 Expression Was: InDifferentialPairClass('90_OHM')
Width Width_pmic [All] p0 off: scope1count=1 scope1_0_kind=Board scope1_0_value=Board scope2count=1 scope2_0_kind=Board scope2_0_value=Board commentlength=57 maxlimit=100 minlimit=4 preferedwidth=5 // Protel DXP Scope 1 Expression Was: WithinRoom('PMIC')
Width Width_50ohm [All] p0: scope1count=1 scope1_0_kind=NetClass scope1_0_value=50_OHM scope2count=1 scope2_0_kind=Board scope2_0_value=Board commentlength=0 maxlimit=11 minlimit=9 preferedwidth=9
Width Width_PWR [All] p0: scope1count=1 scope1_0_kind=NetClass scope1_0_value=PWR scope2count=1 scope2_0_kind=Board scope2_0_value=Board commentlength=0 maxlimit=100 minlimit=10 preferedwidth=25
Width Width_1 [All] p1: maxlimit=100 minlimit=4 preferedwidth=10 minimp=50.000000 maximp=50.000000 favimp=50.000000
Width Width_pmic [WithinRoom('PMIC')] p2: maxlimit=100 minlimit=4 preferedwidth=5 toplayer_prefwidth=4 midlayer1_minwidth=5 midlayer2_minwidth=5 midlayer3_minwidth=5 midlayer4_minwidth=5 bottomlayer_prefwidth=4 minimp=50.000000 maximp=50.000000 favimp=50.000000
Width Width_100 [InDifferentialPairClass('DIIF')] p3: maxlimit=5.2 minlimit=5 preferedwidth=5 toplayer_minwidth=5.2 toplayer_prefwidth=5.2 midlayer1_maxwidth=5 midlayer2_maxwidth=5 midlayer3_maxwidth=5 midlayer4_maxwidth=5 bottomlayer_maxwidth=5 minimp=50.000000 maximp=50.000000 favimp=50.000000
Width Width_90ohm [InDifferentialPairClass('90_OHM')] p4: maxlimit=6 minlimit=5 preferedwidth=5 toplayer_minwidth=5.2 toplayer_maxwidth=5.2 toplayer_prefwidth=5.2 midlayer1_maxwidth=5 midlayer2_maxwidth=5 midlayer3_maxwidth=5 midlayer4_maxwidth=5 bottomlayer_minwidth=6 bottomlayer_prefwidth=6 minimp=50.000000 maximp=50.000000 favimp=50.000000
Width Width_50ohm [InNetClass('50_OHM')] p5: maxlimit=11 minlimit=9 preferedwidth=9 toplayer_minwidth=11 toplayer_prefwidth=11 midlayer1_minwidth=0 midlayer1_maxwidth=0 midlayer1_prefwidth=0 midlayer2_maxwidth=9 midlayer3_maxwidth=9 midlayer4_minwidth=0 midlayer4_maxwidth=0 midlayer4_prefwidth=0 bottomlayer_maxwidth=9 minimp=50.000000 maximp=50.000000 favimp=50.000000
Width Width_PWR [InNetClass('PWR')] p6: maxlimit=100 minlimit=10 preferedwidth=25
Width Width_room1 [All] p7: maxlimit=100 minlimit=10 preferedwidth=20
23 further rules are at their usual default settings.

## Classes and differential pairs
component class AssemblyNote: ZZ1 ZZ2 ZZ3 ZZ4 ZZ5
component class Label: LBL1
net class 90_ohm: XDSET_1_D_N XDSET_1_D_P
component class Logo: Logo1
component class PROC011B_Hardware: "CAUTION HOT SURFACE" "ESD Susceptible" FID1 FID2 FID3 FID4 FID5 FID6 FID7 LBL1 Logo1 Logo2 Logo3 LOGO4 ZZ1 ZZ2 ZZ3 ZZ4 ZZ5
component class FiducialMark: FID1 FID2 FID3 FID4 FID5 FID6 FID7
component class PROC011B_Tempsensor: C91 C92 R3 R5 R167 R168 R196 R197 R198 R199 R200 R201 U12 U13
component class "PROC011B_SOP selection": P2 P3 P4 R88 R89 R92 R93 R95 R96 R97 R98 R99 R101 R112 R113 R114
component class "PROC011B_CAN Interface": C16 C20 C24 C97 J3 R11 R12 R78 R85 R86 R87 R177 R178 R206 R208 S2 U3 U14
component class "PROC011B_XDS110 Interface_1B": C49 C63 C66 C67 C70 C71 R123 R124 R125 R126 R127 R128 R129 R134 R135 R136 R140 R152 R154 R155 U6 U7 Y2
component class "PROC011B_XDS110 Interface_1A": C41 C42 C43 C50 C61 C62 C64 C69 C74 C75 C76 C77 C78 C79 C80 J8 R151 R153 R156 R157 R158 R159 R161 R174 R175 R176 U9 U10
component class "PROC011B_HD Connector": J1 J2 R7 R17 R20 R21 R22 R23 R27 R28 R29 R30 R33 R34 R48 R49 R50 R51 R52 R53 R54 R55 R56 R57 R58 R59 R62 R63 R64 R65 R66 R67 R69 R70 R71 R75 R111 R179 R180 R181 R182 R183 R184 R185 R186 R187 R188 R189 R190 R191 R192
component class "PROC011B_LP Connector": J4 J5 J6 J7 P1 R1 R2 R4 R6 R8 R9 R10 R13 R14 R15 R16 R18 R19 R24 R25 R26 R31 R32 R35 R36 R60 R76 R94 R102 R104 R105 R106 R107 R108 R109 R115 R162 R163 R164 R165 R166 R169 R170 R171 R172 R173
component class "PROC011B_QSPI flash section": C1 C2 R37 R38 R39 R40 R41 R42 R43 R44 R45 U1
component class PROC011B_PMIC: C54 C55 C59 C60 C68 C72 C73 C81 C82 C93 C94 C95 C96 L1 L2 L3 L4 R138 R139 R141 R142 R143 R144 R145 R146 R147 R148 R149 R150 R202 R203 R204 R205 U8
component class PROC011B_Pwr_RST_LEDs: C11 C26 C27 D2 D3 DS1 DS2 DS3 DS4 F1 FB1 FB2 P5 P6 Q1 Q2 R68 R72 R73 R74 R77 R79 R80 R90 R91 R100 R103 R110 R116 R117 R118 R130 R133 R160 SW1 SW2
component class PROC011B_VPP_Supply: C85 C86 C88 P7 R61 R193 R194 U11
component class "PROC011B_LDO_02 (1.3V Output)": C28 C29 C30 C31 C32 C33 C34 C35 C36 C37 C38 C40 C44 C46 R46 R47 R119 R120 R121 R122 R131 R132 U5
component class "PROC011B_LDO_01 (1.8V Output)": C18 C19 C21 C22 C23 C25 R81 R82 R83 R84 U4
component class "PROC011B_Decoupling caps": C3 C4 C5 C6 C7 C10 C12 C13 C14 C17 C39 C45 C47 C48 C51 C52 C53 C56 C57 C58 C65 C83 C84 C87 C89 C90 L5 L6 R137 R195
component class PROC011B_DUT: C8 C9 C15 R210 R211 U2 Y1
component class Header: P1 P2 P3 P4 P5 P7
net class PWR: 3V3_BRD 3V3_MON_XDS_1 5V_IN 5V_UNREG +3.3VD AR_1V8 GND MCU_3V3 MCU_5V PMIC_1V2 PMIC_1V8 PMIC_2V3 PMICOUT_3V3 PMICVIO_3V3 VDDC_1 VPP_1P7
net class DATA0-15: AR_DMM_CLK AR_DMM_SYNC AR_DP0 AR_DP1 AR_DP2 AR_DP3 AR_DP4 AR_DP5 AR_DP6 AR_DP7 AR_DP8 AR_DP9 AR_DP10 AR_DP11 AR_DP12 AR_DP13 AR_DP14 AR_DP15 AR_SYNC_IN
net class LVDS: AR_LVDS_0_N AR_LVDS_0_P AR_LVDS_1_N AR_LVDS_1_P AR_LVDS_CLK_N AR_LVDS_CLK_P AR_LVDS_FRCLK_N AR_LVDS_FRCLK_P
net class QSPI: AR_QSPI_D0 AR_QSPI_D1 AR_QSPI_D2 AR_QSPI_D3 AR_QSPI_SCLK
net class SPI1: AR_CS1 AR_MISO1 AR_MOSI1 AR_SPICLK1
net class SPI2: AR_BSS_LOGGER AR_MSS_LOGGER AR_SCL AR_SDA
net class 50_OHM: PMIC_CLK
net class RF_RX&TX: RX1 RX2 RX3 RX4 TX1 TX2
net class u2_to_MUX: AR_CS1 AR_MISO1 AR_MOSI1 AR_SPICLK1
net class MUX_TO_J1: CS1 MISO1 MOSI1 SPICLK1
differential pair XDSET_1_D: +XDSET_1_D_P -XDSET_1_D_N
differential pair AR_LVDS_0: +AR_LVDS_0_P -AR_LVDS_0_N
differential pair AR_LVDS_1: +AR_LVDS_1_P -AR_LVDS_1_N
differential pair AR_LVDS_CLK: +AR_LVDS_CLK_P -AR_LVDS_CLK_N
differential pair " ": +AR_LVDS_FRCLK_P -AR_LVDS_FRCLK_N

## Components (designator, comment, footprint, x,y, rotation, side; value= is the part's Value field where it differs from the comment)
C1 "GCM188R71C105KA64D" 0603 2199.35,2200.5 r270 top
C2 "CGA2B3X7R1H104K050BB" 0402L 2147.65,2191.4 r270 top
C3 "GCM155R71C224KE02D" 0402L 2466.95,1915.45 r270 top
C4 "GCM155R71C104KA55D" 0402L 2107.72,1629.85 r0 top
C5 "GCM155R71C224KE02D" 0402L 2314.7,1930.1 r270 top
C6 "GCM155R71C104KA55D" 0402L 2137.25,1868.1 r270 top
C7 "GCM155R71C224KE02D" 0402L 2322.75,1782.5 r180 bottom
C8 "C0603X7S1A104K030BC" 0201_033 2239.75,1728.5 r270 bottom
C9 "GJM1555C1H4R7BB01D" 0402L 1945.11,1487.23 r90 top
C10 "GCM155R71C224KE02D" 0402L 2570.55,1392.35 r180 top
C11 "GCM155R71C104KA55D" 0402L 300.05,1447.4 r270 top
C12 "GCM155R71C224KE02D" 0402L 2269.95,1371.7 r90 top
C13 "GCM188R71C105KA64D" 0603 2329.25,1350.4 r90 top
C14 "GCM188R71C105KA64D" 0603 2187.2,1351.9 r90 top
C15 "GJM1555C1H4R7BB01D" 0402L 2056.75,1342.9 r0 top
C16 "C0402C104K8RACTU" 0402L 1072.35,1082.5 r0 top
C17 "GCM21BR71A106KE22L" 0805_HV 2275.85,1185.1 r180 top
C18 "GCM188R71C474KA55D" 0603 2132.62,1189.37 r0 top
C19 "GCM21BR71A106KE22L" 0805_HV 2275.7,1105.17 r180 top
C20 "C0402C104K8RACTU" 0402L 1069.94,961.35 r0 top
C21 "CGA2B3X7R1H104K050BB" 0402L 2243.85,984.8 r180 top
C22 "GCM188R71C474KA55D" 0603 2031.22,952.77 r0 top
C23 "GCM21BR71A106KE22L" 0805_HV 2188.35,924.38 r180 top
C24 "C1005X7R1H472K050BA" 0402L 1219.85,853.6 r90 top
C25 "CGA5L1X7R0J226M160AC" 1206_180 2212.6,838.73 r180 top
C26 "T491B476K010AT" 3528-21 1780.45,162.15 r270 top
C27 "T491B476K010AT" 3528-21 1637.05,160.95 r270 top
C28 "CGA2B3X8R1H103K050BB" 0402L 1835.75,2055.5 r0 bottom
C29 "CGA2B3X8R1H103K050BB" 0402L 1712.22,2076.55 r270 bottom
C30 "CGA5L1X7R0J226M160AC" 1206_180 1504.75,1959 r270 bottom
C31 "CGA5L1X7R0J226M160AC" 1206_180 1412.95,1958.75 r270 bottom
C32 "GCM21BR71A106KE22L" 0805_HV 1590.7,1957.5 r270 bottom
C33 "GCM188R71C105KA64D" 0603 1909.9,1967.1 r270 bottom
C34 "GCM21BR71A106KE22L" 0805_HV 2062.5,1969.7 r270 bottom
C35 "GCM21BR71A106KE22L" 0805_HV 1980.4,1969.7 r270 bottom
C36 "GCM188R71C105KA64D" 0603 1905.28,1805.35 r90 bottom
C37 "GCM21BR71A106KE22L" 0805_HV 1975.28,1804.65 r90 bottom
C38 "GCM21BR71A106KE22L" 0805_HV 2079.25,1802.5 r90 bottom
C39 "GCM155R71C224KE02D" 0402L 2564.8,1757.8 r180 bottom
C40 "GCM21BR71A106KE22L" 0805_HV 1602.7,1794.8 r90 bottom
C41 "C1005X7S0J105M050BC" 0402L 661.05,1794.35 r270 bottom
C42 "C0402C104K8RACTU" 0402L 620.97,1794.35 r270 bottom
C43 "C0402C104K8RACTU" 0402L 465.27,1792.35 r270 bottom
C44 "CGA2B3X8R1H103K050BB" 0402L 1708.92,1740.75 r90 bottom
C45 "GCM21BR71A106KE22L" 0805_HV 2672.85,1737.55 r0 bottom
C46 "CGA2B3X8R1H103K050BB" 0402L 1831.25,1719.02 r0 bottom
C47 "GCM155R71C224KE02D" 0402L 2565.2,1716.6 r180 bottom
C48 "GCM155R71C224KE02D" 0402L 2381.75,1810.9 r90 bottom
C49 "C0402C104K8RACTU" 0402L 997.1,1644.4 r180 bottom
C50 "C1005X7R1E103K050BB" 0402L 248.7,1611.2 r270 bottom
C51 "GCM155R71C224KE02D" 0402L 2539.9,1585.4 r90 bottom
C52 "GCM21BR71A106KE22L" 0805_HV 2600.9,1583.9 r90 bottom
C53 "GCM155R71C224KE02D" 0402L 2196.1,1576.5 r0 bottom
C54 "GCM31CR71A226KE02" 1206_180 1698.9,1582.2 r90 bottom
C55 "GCM31CR71A226KE02" 1206_180 1606.8,1582.2 r90 bottom
C56 "GCM155R71C224KE02D" 0402L 2260.9,1475.8 r0 bottom
C57 "GCM155R71C224KE02D" 0402L 2642.95,1422.45 r90 bottom
C58 "GCM21BR71A106KE22L" 0805_HV 2560.95,1444.45 r90 bottom
C59 "GCM21BR71A106KE22L" 0805_HV 1583.6,1434.6 r180 bottom
C60 "GCM21BR71A106KE22L" 0805_HV 1724.7,1434.4 r0 bottom
C61 "C1005X7S0J105M050BC" 0402L 230.4,1402.56 r0 bottom
C62 "C1005X7S0J105M050BC" 0402L 1012.1,1364 r180 bottom
C63 "GRM1555C1H8R0DA01D" 0402L 1091,1354.35 r180 bottom
C64 "C0402C104K8RACTU" 0402L 1012.4,1320.8 r180 bottom
C65 "GCM21BR71A106KE22L" 0805_HV 2579.35,1302.45 r90 bottom
C66 "C0402C103K4RACTU" 0402L 229.94,1292.6 r0 bottom
C67 "C0402C104K8RACTU" 0402L 230,1251.3 r0 bottom
C68 "GCM155R71C224KE02D" 0402L 1842.2,1223.5 r180 bottom
C69 "C0402C103K4RACTU" 0402L 230.4,1166.06 r0 bottom
C70 "GRM1555C1H8R0DA01D" 0402L 1137.94,1122.7 r180 bottom
C71 "C0402C104K8RACTU" 0402L 916.75,1173 r180 top
C72 "GCM21BR71A106KE22L" 0805_HV 1721.4,1031.2 r0 bottom
C73 "GCM21BR71A106KE22L" 0805_HV 1582.6,1031.2 r180 bottom
C74 "C1005X7S1A225K050BC" 0402_065L 619.35,1019.65 r90 bottom
C75 "C0402C104K8RACTU" 0402L 576.43,1019.65 r90 bottom
C76 "C0402C104K8RACTU" 0402L 464.67,1024.35 r90 bottom
C77 "C1005X7S1A225K050BC" 0402_065L 210.57,1021.65 r270 bottom
C78 "04025A150FAT2A" 0402L 169.85,1021.65 r270 bottom
C79 "C0402C104K8RACTU" 0402L 128.37,1021.35 r270 bottom
C80 "C1005X7S1A225K050BC" 0402_065L 87.35,1021 r270 bottom
C81 "GCM31CR71A226KE02" 1206_180 1603.6,881.5 r270 bottom
C82 "GCM31CR71A226KE02" 1206_180 1698.95,881.5 r270 bottom
C83 "GCM21BR71A106KE22L" 0805_HV 2579.15,1302.15 r90 top
C84 "GCM155R71C224KE02D" 0402L 2017.75,1584.5 r0 top
C85 "C1005X7S0J105M050BC" 0402L 500.65,1103 r180 top
C86 "C1005X7S1A225K050BC" 0402_065L 512.55,1291.6 r180 top
C87 "GCM188R70J225KE22D" 0603 2364.55,1953.9 r270 top
C88 "C0402C330J5GAC" 0402L 628.75,1062.9 r0 top
C89 "GCM188R70J225KE22D" 0603 2084.85,1891.4 r270 top
C90 "GCM155R71C224KE02D" 0402L 2257.75,1272.5 r90 top
C91 "C0402C104K8RACTU" 0402L 1821.15,1168.6 r90 top
C92 "C0402C104K8RACTU" 0402L 366.35,1078.7 r90 top
C93 "CGA2B2NP01H391J050BA" 0402L 1454.45,1436.4 r270 bottom
C94 "CGA2B2NP01H391J050BA" 0402L 1814.05,1360.8 r90 bottom
C95 "CGA2B2NP01H391J050BA" 0402L 1453.15,1028.7 r90 bottom
C96 "CGA2B2NP01H391J050BA" 0402L 1877.85,1032.6 r90 bottom
C97 "C0402C104K8RACTU" 0402L 1002.23,1361.93 r0 top locked
"CAUTION HOT SURFACE" "CAUTION HOT SURFACE" IEC_HotSurface_Small 1670.8,1747.28 r0 top
D2 "SMS3923-040LF" SOD-882 156.48,1267.97 r0 top
D3 "SZP6SMB6.8AT3G" SMB 1627.39,859 r0 top
DS1 "TLMS1000-GS08" TLMX1000_RED 237.46,774.63 r90 top
DS2 "TLMS1000-GS08" TLMX1000_RED 358.35,774.37 r90 top
DS3 "TLMY1000-GS08" TLMX1000_YELLOW 119.78,774.31 r90 top
DS4 "TLMY1000-GS08" TLMX1000_YELLOW 358.35,566.96 r90 top
"ESD Susceptible" "ESD Susceptible" ESD_Overlay_Small 931.05,585.3 r0 top
F1 "0440005.WR" 1206 1469.23,458.38 r180 top
FB1 "BLM21PG300SH1D" 0805_HV 1558.05,646.4 r0 top
FB2 "BLM21PG300SH1D" 0805_HV 1557.93,727.63 r0 top
FID1 "Fiducial" FIDUCIAL10-20 298.75,2450 r90 top
FID2 "Fiducial" FIDUCIAL10-20 3110.08,2018.14 r90 top
FID3 "Fiducial" FIDUCIAL10-20 298.75,122 r90 top
FID4 "Fiducial" FIDUCIAL10-20 298.75,2450 r90 bottom
FID5 "Fiducial" FIDUCIAL10-20 3110.08,2018.14 r90 bottom
FID6 "Fiducial" FIDUCIAL10-20 298.75,122 r90 bottom
FID7 "Fiducial" Fiducial10-20 1956.75,1168.5 r90 top
J1 "QSH-030-01-L-D-A" SAMTEC_QSH-030-01-X-D-A 916.39,2048.76 r270 top
J2 "128-0711-201" JOHNSON_128-0711-201 2261.46,456.22 r0 top
J3 "OSTTE030161" ON-SHORE_OSTTE030161 773.35,137.22 r0 top
J4 "SSM-103-S-SV" SAMTEC_SSM-103-X-SV 1830.25,2322 r0 bottom
J5 "SSM-110-S-DV" SAMTEC_SSM-110-X-DV 1080.25,2272 r0 bottom
J6 "SSM-110-S-DV" SAMTEC_SSM-110-X-DV 1080.25,572 r0 bottom
J7 "SSM-103-S-SV" SAMTEC_SSM-103-X-SV 1830.25,522 r0 bottom
J8 "105017-0001" CONN_105017-0001 2047.75,110.23 r180 bottom
L1 "DFE252012P-R47M=P2" DFE252012P 1796.8,1539.8 r90 bottom
L2 "DFE252012P-R47M=P2" DFE252012P 1510.6,1539.4 r90 bottom
L3 "DFE252012P-R47M=P2" DFE252012P 1796.3,924.3 r270 bottom
L4 "DFE252012P-R47M=P2" DFE252012P 1504.3,924.3 r270 bottom
L5 "DFE252012P-R47M=P2" DFE252012P 2242.55,1103.8 r90 bottom
L6 "DFE252012P-R47M=P2" DFE252012P 1655.35,1985.35 r0 top
LBL1 "Size: 0.65\" x 0.20 \"" Label_650x200 2605.12,127.94 r0 top
Logo1 "Texas Instruments" TI_Stacked_Overlay_Small 1222,1528.25 r0 top
Logo2 "WEEE logo" WEEE_Minimum 3022.23,1644.67 r180 bottom
Logo3 "FCC disclaimer" FCC_disclaimer 2392.54,1816.41 r180 bottom
LOGO4 "CE Mark" CE_Mark_5mm 350.12,2185.2 r180 bottom
P1 "TSW-103-07-T-S" SAMTEC_TSW-103-07-T-S 109.02,1908.65 r270 top
P2 "TSW-102-07-G-S" TSW-102-07-X-S 715.19,882.25 r90 top
P3 "TSW-102-07-G-S" TSW-102-07-X-S 511.75,881.92 r90 top
P4 "TSW-102-07-G-S" TSW-102-07-X-S 921.19,881.25 r90 top
P5 "TSW-102-07-G-S" TSW-102-07-X-S 1711,374.56 r0 top
P6 "PJ-002AH" CUI_PJ-002AH 1287.75,174.5 r270 top
P7 "TSW-102-07-G-S" TSW-102-07-X-S 274.69,1958.65 r270 top
Q1 "BSS123" SOT-23 223.33,635.25 r90 top
Q2 "BSS123" SOT-23 223.37,634.67 r90 bottom
R1 "CRCW02010000Z0ED" 0201_Silk 1212.55,2509.5 r270 bottom
R2 "CRCW02010000Z0ED" 0201_Silk 1032.8,2405.22 r270 top
R3 "CRCW040210K0FKED" 0402L 1648.05,1167.6 r180 top
R4 "CRCW02010000Z0ED" 0201_Silk 1125.3,2405.22 r270 top
R5 "CRCW02010000Z0ED" 0201_Silk 1655.65,1207 r0 top
R6 "CRCW02010000Z0ED" 0201_Silk 1230.8,2405.22 r270 top
R7 "CRCW02010000Z0ED" 0201_Silk 1264,2405.22 r270 top
R8 "CRCW02010000Z0ED" 0201_Silk 1417.26,2493.5 r180 bottom
R9 "CRCW02010000Z0ED" 0201_Silk 932.5,2404.22 r270 top
R10 "CRCW02010000Z0ED" 0201_Silk 1342,2404.22 r270 top
R11 "ERJ-2GE0R00X" 0402L 1262.95,1221.42 r0 top
R12 "ERJ-2GE0R00X" 0402L 1128.91,1220.7 r180 top
R13 "CRCW040210K0FKED" 0402L 1301.15,2396.55 r270 top
R14 "CRCW0402100KFKED" 0402L 1145.65,2505.1 r180 bottom
R15 "CRCW040210K0FKED" 0402L 1216.75,2300.35 r270 top
R16 "CRCW040210K0FKED" 0402L 751.75,2008.5 r180 bottom
R17 "CRCW02010000Z0ED" 0201_Silk 1163,2293.22 r270 top
R18 "CRCW02010000Z0ED" 0201_Silk 1130.96,2292.57 r270 top
R19 "CRCW02010000Z0ED" 0201_Silk 522,2292.22 r270 top
R20 "CRCW02010000Z0ED" 0201_Silk 554.86,2292.22 r270 top
R21 "CRCW02010000Z0ED" 0201_Silk 587.1,2292.22 r270 top
R22 "CRCW02010000Z0ED" 0201_Silk 652.86,2292.22 r270 top
R23 "CRCW02010000Z0ED" 0201_Silk 685.36,2292.22 r270 top
R24 "CRCW02010000Z0ED" 0201_Silk 743.85,2048.1 r180 bottom
R25 "CRCW02010000Z0ED" 0201_Silk 858.55,2046.3 r180 bottom
R26 "CRCW02010000Z0ED" 0201_Silk 969.45,2292.1 r270 top
R27 "CRCW02010000Z0ED" 0201_Silk 1001.55,2292 r270 top
R28 "CRCW02010000Z0ED" 0201_Silk 1034.25,2291.9 r270 top
R29 "CRCW02010000Z0ED" 0201_Silk 1066.58,2292.22 r270 top
R30 "CRCW02010000Z0ED" 0201_Silk 1098.5,2292.22 r270 top
R31 "CRCW02010000Z0ED" 0201_Silk 1279.5,2292.22 r270 top
R32 "CRCW02010000Z0ED" 0201_Silk 1380.3,2292.22 r270 top
R33 "CRCW02010000Z0ED" 0201_Silk 620.14,2291.78 r270 top
R34 "CRCW20100000Z0EF" 2010 1528.2,2233.77 r0 top
R35 "CRCW02010000Z0ED" 0201_Silk 1429.5,2139.22 r90 top
R36 "CRCW02010000Z0ED" 0201_Silk 1530,2139.22 r90 top
R37 "ERJ-2GE0R00X" 0402L 2252.25,2189.9 r270 top
R38 "CRCW040247K5FKED" 0402L 1790.55,2184.34 r180 top
R39 "CRCW020133R2FNED" 0201_Silk 1759.65,2107 r90 top
R40 "CRCW020133R2FNED" 0201_Silk 2152.43,2117.35 r0 top
R41 "CRCW040210K0FKED" 0402L 2221.3,2113.48 r0 top
R42 "CRCW020133R2FNED" 0201_Silk 1811.25,2105.3 r90 top
R43 "CRCW040210K0FKED" 0402L 1785.95,2054.5 r180 top
R44 "CRCW020133R2FNED" 0201_Silk 2152.43,2082.85 r0 top
R45 "CRCW020133R2FNED" 0201_Silk 2153.43,2036.35 r0 top
R46 "CRCW040210K0FKED" 0402L 1588.35,1887.8 r270 top
R47 "CRCW040210K0FKED" 0402L 1545.15,1888.4 r90 top
R48 "CRCW02010000Z0ED" 0201_Silk 578.36,1774.22 r270 top
R49 "CRCW02010000Z0ED" 0201_Silk 611,1774.22 r270 top
R50 "CRCW02010000Z0ED" 0201_Silk 643.5,1774.22 r270 top
R51 "CRCW02010000Z0ED" 0201_Silk 676,1774.22 r270 top
R52 "CRCW02010000Z0ED" 0201_Silk 708.5,1774.22 r270 top
R53 "CRCW02010000Z0ED" 0201_Silk 741,1774.22 r270 top
R54 "CRCW020120R0FNED" 0201_033 1086.75,2036.5 r90 bottom
R55 "CRCW020120R0FNED" 0201_033 1053.75,2036.3 r90 bottom
R56 "CRCW020120R0FNED" 0201_033 1021.25,2035.8 r90 bottom
R57 "CRCW020120R0FNED" 0201_033 988.35,2035.8 r90 bottom
R58 "CRCW02010000Z0ED" 0201_Silk 903.3,1774.22 r270 top
R59 "CRCW02010000Z0ED" 0201_Silk 935.8,1774.22 r270 top
R60 "CRCW02010000Z0ED" 0201_Silk 790.75,2397.5 r270 top
R61 "CRCW040214K0FKED" 0402L 628.55,1103.6 r180 top
R62 "CRCW02010000Z0ED" 0201_Silk 1032.6,1774.22 r270 top
R63 "CRCW02010000Z0ED" 0201_Silk 1064.86,1774.22 r270 top
R64 "CRCW02010000Z0ED" 0201_Silk 1129.36,1774.22 r270 top
R65 "CRCW02010000Z0ED" 0201_Silk 1162,1774.22 r270 top
R66 "CRCW02010000Z0ED" 0201_Silk 1194.5,1774.22 r270 top
R67 "CRCW02010000Z0ED" 0201_Silk 1227,1774.22 r270 top
R68 "ERJ-2GEJ101X" 0402L 348.79,1715.65 r90 top
R69 "CRCW02010000Z0ED" 0201_Silk 1162,1714.22 r270 top
R70 "CRCW02010000Z0ED" 0201_Silk 1194.08,1714.22 r270 top
R71 "CRCW02010000Z0ED" 0201_Silk 1227.08,1714.22 r270 top
R72 "CRCW02010000Z0ED" 0201_Silk 295.25,1623.75 r90 top
R73 "CRCW040210K0FKED" 0402L 294.8,1553.42 r90 top
R74 "CRCW040210K0FKED" 0402L 154.4,1383.64 r180 top
R75 "CRCW02010000Z0ED" 0201_Silk 1346.75,1343.5 r270 top
R76 "CRCW02010000Z0ED" 0201_Silk 1379.75,1343.5 r270 top
R77 "ERJ-2GEJ101X" 0402L 75.01,1351.35 r270 top
R78 "ERJ-2GE0R00X" 0402L 1072.75,1042.5 r180 top
R79 "ERJ-2GEJ101X" 0402L 345,1315.64 r180 top
R80 "ERJ-2GEJ101X" 0402L 75.49,1249.65 r90 top
R81 "CRCW040210K0FKED" 0402L 2062.64,1239.67 r0 top
R82 "CRCW040212K7FKED" 0402L 2138.06,1239.63 r0 top
R83 "CRCW040210K0FKED" 0402L 2000.1,1054.52 r180 top
R84 "CRCW040210K0FKED" 0402L 2000.1,1013.72 r0 top
R85 "CRCW040261R9FKED" 0402L 1260.75,853.3 r90 top
R86 "CRCW040210K0FKED" 0402L 1349.05,957.2 r270 top
R87 "CRCW040261R9FKED" 0402L 1179.45,853.9 r270 top
R88 "CRCW040282K5FKED" 0402L 1068.87,826.35 r270 top
R89 "CRCW040210K0FKED" 0402L 1109.33,826.05 r270 top
R90 "ERJ-2GEJ361X" 0402L 303.21,900.29 r90 top
R91 "CRCW040210K0FKED" 0402L 245.27,899.97 r90 top
R92 "CRCW04027K87FKED" 0402L 1068.37,748.35 r270 top
R93 "CRCW0402750RFKED" 0402L 1108.57,748.35 r270 top
R94 "CRCW02010000Z0ED" 0201_Silk 931,694.78 r90 top
R95 "CRCW04027K87FKED" 0402L 751.57,687.05 r90 top
R96 "CRCW040282K5FKED" 0402L 711.53,686.75 r270 top
R97 "ERJ-2GE0R00X" 0402L 387.75,671.65 r90 top
R98 "CRCW040210K0FKED" 0402L 428.57,671.65 r90 top
R99 "CRCW04027K87FKED" 0402L 512.37,671.65 r90 top
R100 "ERJ-2GEJ511X" 0402L 345.66,671.56 r270 top
R101 "CRCW0402750RFKED" 0402L 469.73,671.35 r90 top
R102 "CRCW02010000Z0ED" 0201_Silk 1333,662.78 r90 top
R103 "ERJ-2GEJ511X" 0402L 110.32,662.57 r180 top
R104 "CRCW02010000Z0ED" 0201_Silk 830.5,661.78 r90 top
R105 "CRCW02010000Z0ED" 0201_Silk 1032.5,661.78 r90 top
R106 "CRCW02010000Z0ED" 0201_Silk 1133,661.78 r90 top
R107 "ERJ-2GE0R00X" 0402L 1232.5,661.78 r90 top
R108 "CRCW02010000Z0ED" 0201_Silk 1433.1,661.58 r90 top
R109 "CRCW02010000Z0ED" 0201_Silk 1470.6,661.58 r90 top
R110 "CRCW0402100KFKED" 0402L 110.47,622.27 r180 top
R111 "CRCW02010000Z0ED" 0201_Silk 2261.61,618.67 r270 top
R112 "CRCW0402750RFKED" 0402L 752.07,610.05 r270 top
R113 "CRCW040210K0FKED" 0402L 711.67,610.05 r90 top
R114 "CRCW040282K5FKED" 0402L 512.27,595.65 r90 top
R115 "CRCW20100000Z0EF" 2010 601.48,593.55 r270 top
R116 "ERJ-2GEJ511X" 0402L 110.53,578.83 r0 top
R117 "ERJ-2GEJ511X" 0402L 411.36,554.65 r90 top
R118 "CRCW20100000Z0EF" 2010 1692.3,542.25 r0 top
R119 "ERJ-2GE0R00X" 0402L 1775.75,2143.5 r180 bottom
R120 "ERJ-2GE0R00X" 0402L 1670.75,2096 r270 bottom
R121 "CRCW04023K00FKED" 0402L 1778.02,2033.39 r270 bottom
R122 "CRCW04021K96FKED" 0402L 1836.03,2014.92 r0 bottom
R123 "CRCW04021K00FKED" 0402L 860.03,1794.65 r90 bottom
R124 "CRCW04021K00FKED" 0402L 740.47,1794.35 r270 bottom
R125 "CRCW04024K87FKED" 0402L 780.27,1794.35 r270 bottom
R126 "CRCW04021K00FKED" 0402L 820.43,1794.65 r90 bottom
R127 "CRCW04021K00FKED" 0402L 700.87,1794.35 r270 bottom
R128 "ERJ-2GE0R00X" 0402L 349.25,1791.35 r270 bottom
R129 "ERJ-2GE0R00X" 0402L 389.75,1791 r270 bottom
R130 "MCT06030Z0000ZP500" 0603 1503.06,1761.21 r180 bottom
R131 "CRCW04021K96FKED" 0402L 1831.49,1759.28 r0 bottom
R132 "CRCW04023K00FKED" 0402L 1773.22,1740.85 r90 bottom
R133 "MCT06030Z0000ZP500" 0603 1468.85,1729.7 r90 bottom
R134 "CRCW040249R9FKED" 0402L 997.4,1603.1 r0 bottom
R135 "CRCW02010000Z0ED" 0201_Silk 237.53,1528.69 r0 bottom
R136 "CRCW02010000Z0ED" 0201_Silk 237.53,1496.79 r0 bottom
R137 "MCT06030Z0000ZP500" 0603 2731.32,1440.69 r270 bottom
R138 "CRCW0402100KFKED" 0402L 1480.85,1272.4 r0 bottom
R139 "CRCW04021K96FKED" 0402L 1967.75,1350.04 r180 bottom
R140 "CRCW04021K00FKED" 0402L 230.4,1362.02 r0 bottom
R141 "ERJ-2GE0R00X" 0402L 1508.85,1315.4 r180 bottom
R142 "ERJ-2RKF4991X" 0402L 1966.1,1309.54 r180 bottom
R143 "CRCW04024K99FKED" 0402L 1878.25,1284.3 r0 bottom
R144 "CRCW02010000Z0ED" 0201_Silk 1482.75,1219.6 r180 bottom
R145 "CRCW040210K0FKED" 0402L 1936.19,1240.5 r270 bottom
R146 "CRCW02010000Z0ED" 0201_Silk 1477.35,1169.5 r0 bottom
R147 "CRCW04024K99FKED" 0402L 1877.75,1183 r0 bottom
R148 "CRCW040210K0FKED" 0402L 1977.75,1165 r90 bottom
R149 "ERJ-2GEJ102X" 0402L 2018.89,1164.65 r270 bottom
R150 "ERJ-2RKF4991X" 0402L 1936.49,1164.65 r270 bottom
R151 "CRCW0402330KFKED" 0402L 230.4,1123.54 r180 bottom
R152 "ERJ-2GE0R00X" 0402L 923.3,1210 r0 top
R153 "CRCW0402330KFKED" 0402L 230.4,1080.24 r0 bottom
R154 "ERJ-2GEJ101X" 0402L 898.75,1098.5 r270 top
R155 "CRCW040210K0FKED" 0402L 795.53,1023.65 r90 bottom
R156 "CRCW040249K9FKED" 0402L 260.78,901.69 r90 bottom
R157 "CRCW040230K0FKED" 0402L 301.95,901.35 r270 bottom
R158 "CRCW0402100KFKED" 0402L 168.43,752.35 r90 bottom
R159 "ERJ-2GE0R00X" 0402L 127.18,752.21 r90 bottom
R160 "ERJ-2GEJ511X" 0402L 110.45,578.41 r0 bottom
R161 "MCT06030Z0000ZP500" 0603 2162.75,420 r90 bottom
R162 "CRCW02010000Z0ED" 0201_Silk 1573,334.78 r90 bottom
R163 "CRCW02010000Z0ED" 0201_Silk 1493,334.22 r90 bottom
R164 "CRCW02010000Z0ED" 0201_Silk 1455.5,334.22 r90 bottom
R165 "CRCW02010000Z0ED" 0201_Silk 997.75,1774.5 r90 top
R166 "CRCW02010000Z0ED" 0201_Silk 935.5,331.78 r90 bottom
R167 "CRCW02010000Z0ED" 0201_Silk 1797.35,1115.1 r180 top
R168 "CRCW02010000Z0ED" 0201_Silk 1819.35,1222.4 r0 top
R169 "CRCW02010000Z0ED" 0201_Silk 787.88,331.78 r90 bottom
R170 "CRCW040210K0FKED" 0402L 1530.77,326.35 r270 bottom
R171 "CRCW040210K0FKED" 0402L 1418.12,326.35 r270 bottom
R172 "CRCW0402100KFKED" 0402L 972.93,323.65 r90 bottom
R173 "CRCW0402100KFKED" 0402L 862.63,323.65 r90 bottom
R174 "CRCW040230K0FKED" 0402L 2315.15,144.39 r90 bottom
R175 "MCT06030Z0000ZP500" 0603 1773.75,223 r90 bottom
R176 "MCT06030Z0000ZP500" 0603 98.75,906 r270 top
R177 "CRCW040210K0FKED" 0402L 1349.25,1032.85 r270 top
R178 "ERJ-2GE0R00X" 0402L 1303.55,853.1 r270 top
R179 "CRCW020120R0FNED" 0201_033 913.75,2293 r270 top
R180 "CRCW020120R0FNED" 0201_033 880.45,2293.2 r270 top
R181 "CRCW020120R0FNED" 0201_033 856.25,2396.8 r270 top
R182 "CRCW020120R0FNED" 0201_033 847.75,2287.5 r270 top
R183 "CRCW020120R0FNED" 0201_033 823.75,2397.2 r270 top
R184 "CRCW020120R0FNED" 0201_033 814.75,2292.5 r270 top
R185 "CRCW020120R0FNED" 0201_033 752.75,2342.5 r0 top
R186 "CRCW020120R0FNED" 0201_033 781.05,2292.5 r270 top
R187 "CRCW020120R0FNED" 0201_033 747.75,2292.5 r270 top
R188 "CRCW020120R0FNED" 0201_033 697.75,1482.6 r90 top
R189 "CRCW020120R0FNED" 0201_033 627.75,1482.6 r90 top
R190 "CRCW020120R0FNED" 0201_033 767.75,1482.6 r90 top
R191 "CRCW020120R0FNED" 0201_033 662.75,1482.6 r90 top
R192 "CRCW020120R0FNED" 0201_033 732.75,1482.6 r90 top
R193 "PNM0402E3502BST1" 0402L 647.65,1177.51 r270 top
R194 "CRCW040210K0FKED" 0402L 647.65,1254.29 r270 top
R195 "MCT06030Z0000ZP500" 0603 1834.95,1894.6 r270 top
R196 "ERJ-2GE0R00X" 0402L 1890.65,1145 r270 top
R197 "CRCW040210K0FKED" 0402L 280.55,1178.9 r270 top
R198 "CRCW02010000Z0ED" 0201_Silk 406.35,1238.3 r180 top
R199 "CRCW02010000Z0ED" 0201_Silk 403.05,1097.3 r270 top
R200 "ERJ-2GE0R00X" 0402L 325.45,1078.8 r270 top
R201 "CRCW02010000Z0ED" 0201_Silk 287.65,1086.7 r270 top
R202 "CRCW04023R83FKED" 0402L 1494.45,1436.4 r90 bottom
R203 "CRCW04023R83FKED" 0402L 1814.25,1436.3 r90 bottom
